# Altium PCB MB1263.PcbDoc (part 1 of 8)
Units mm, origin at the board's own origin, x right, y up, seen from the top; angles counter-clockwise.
Board outline 86 x 120 mm, 6 copper layers (Top Layer, Signal Layer 1, Signal Layer 2, Signal Layer 3, Signal Layer 4, Bottom Layer), stack 1.556 mm thick; 392 components, 421 nets, 1978 pads, 1444 vias.
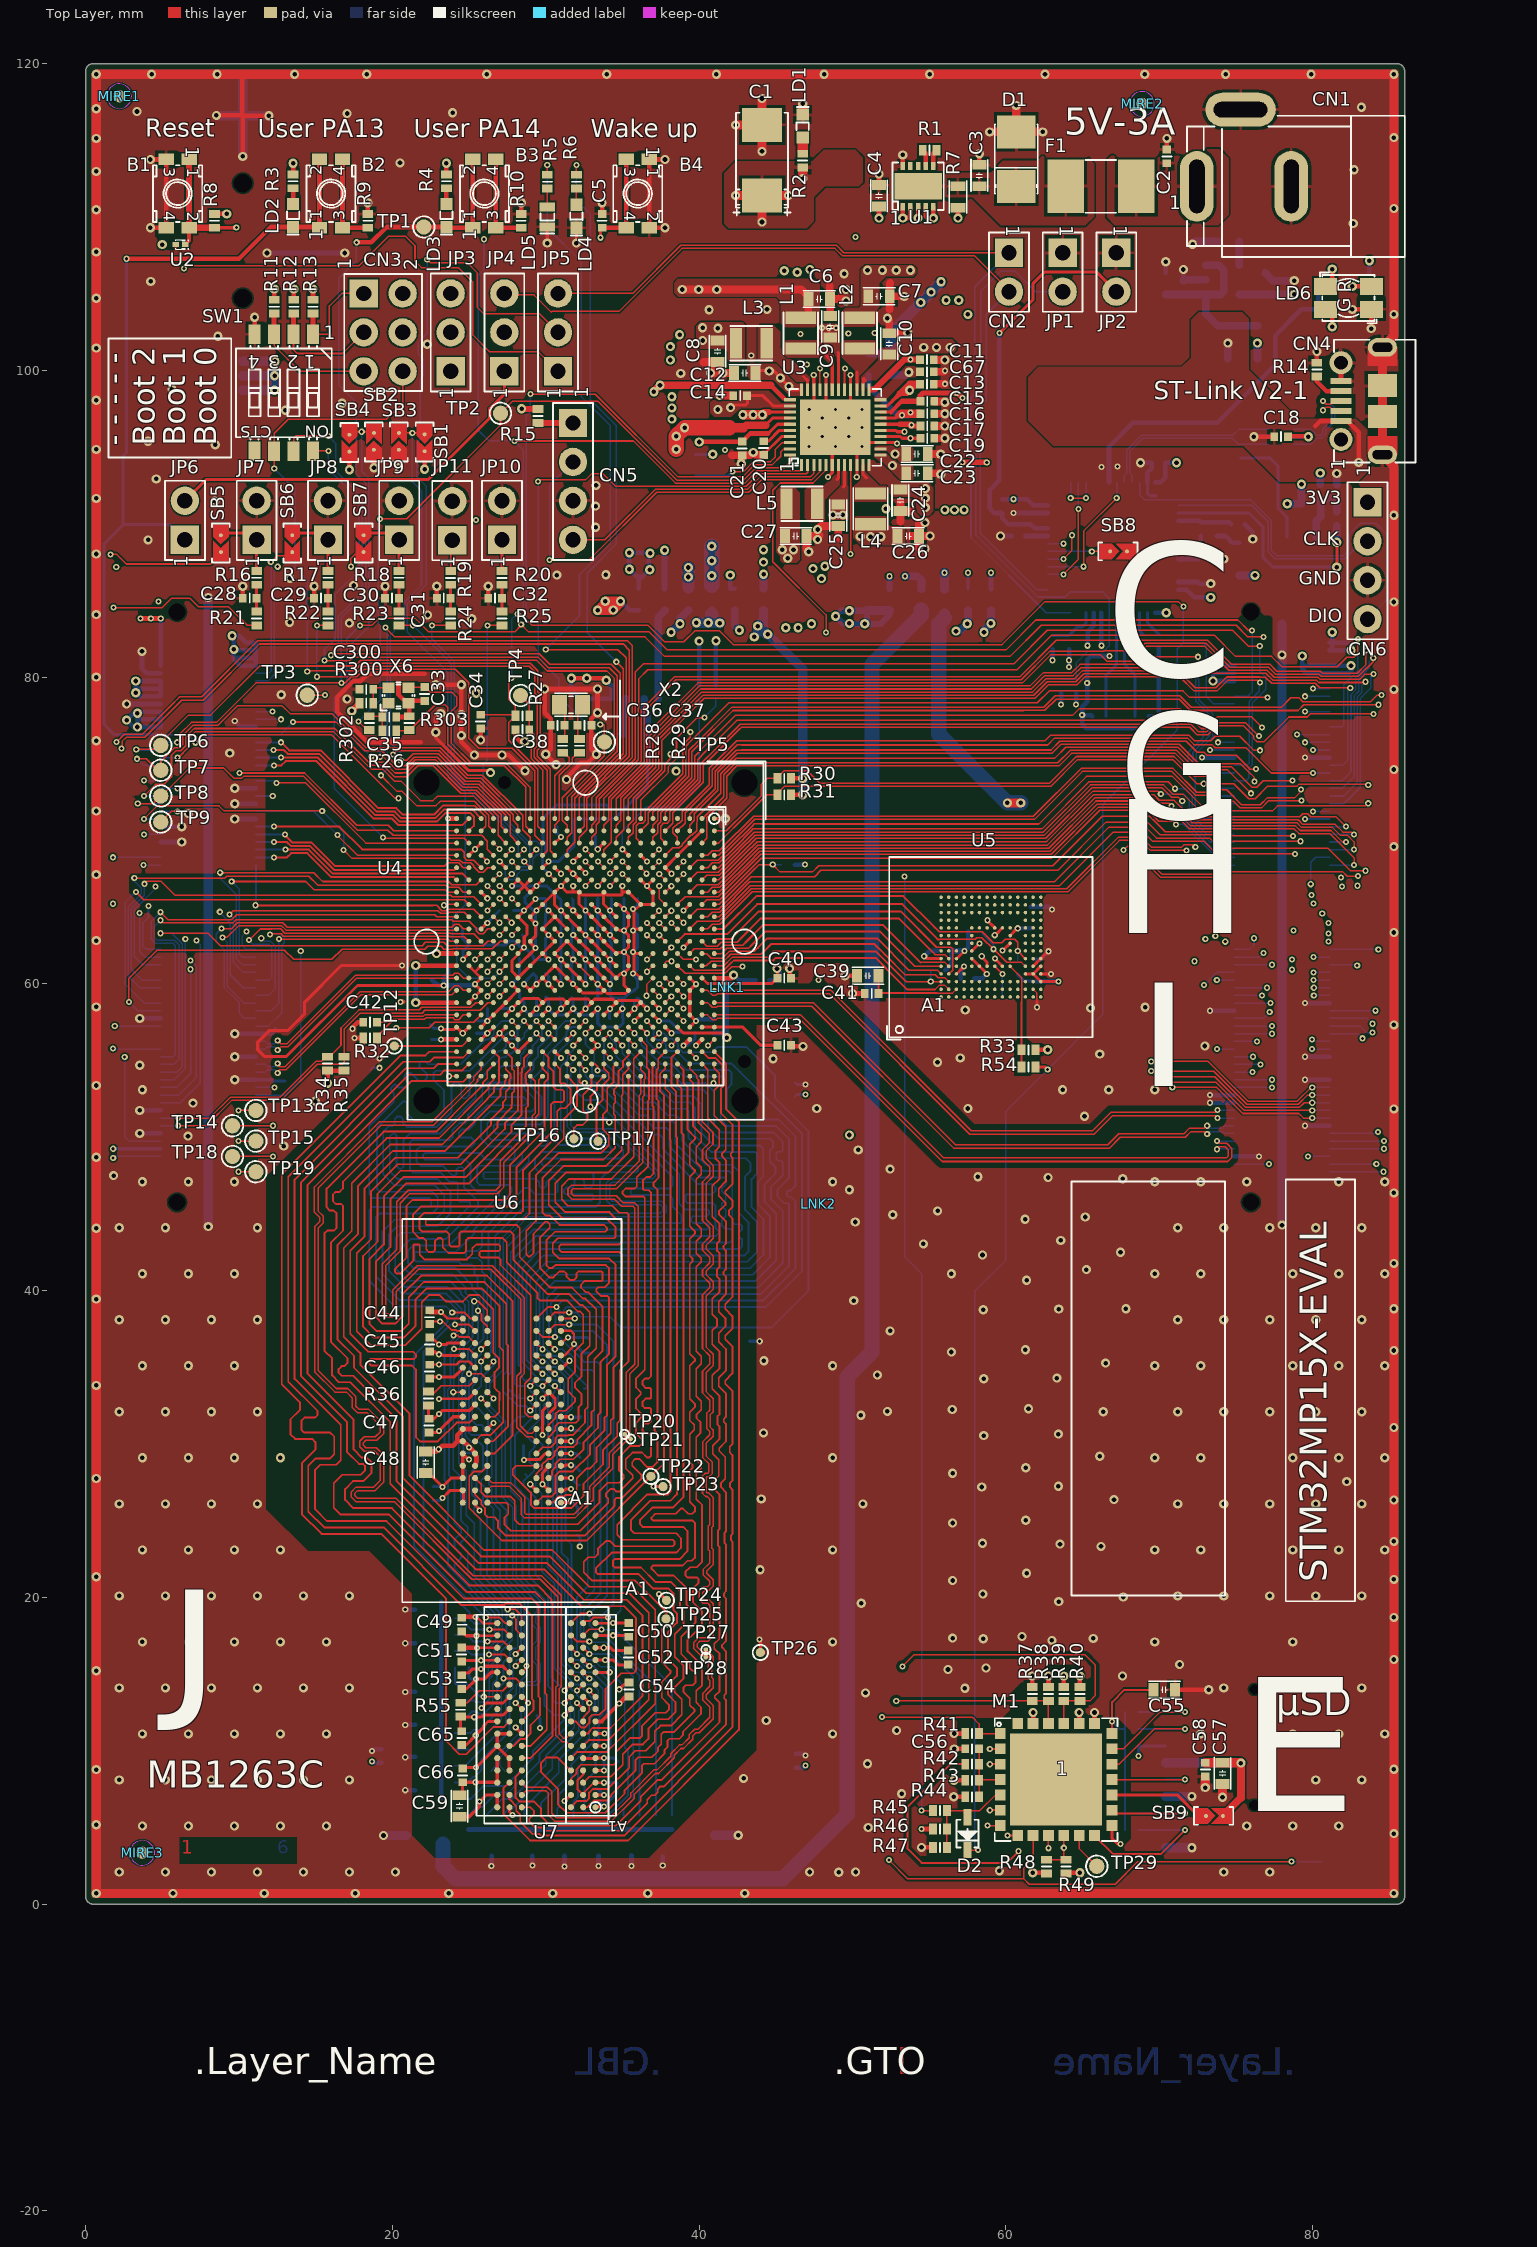
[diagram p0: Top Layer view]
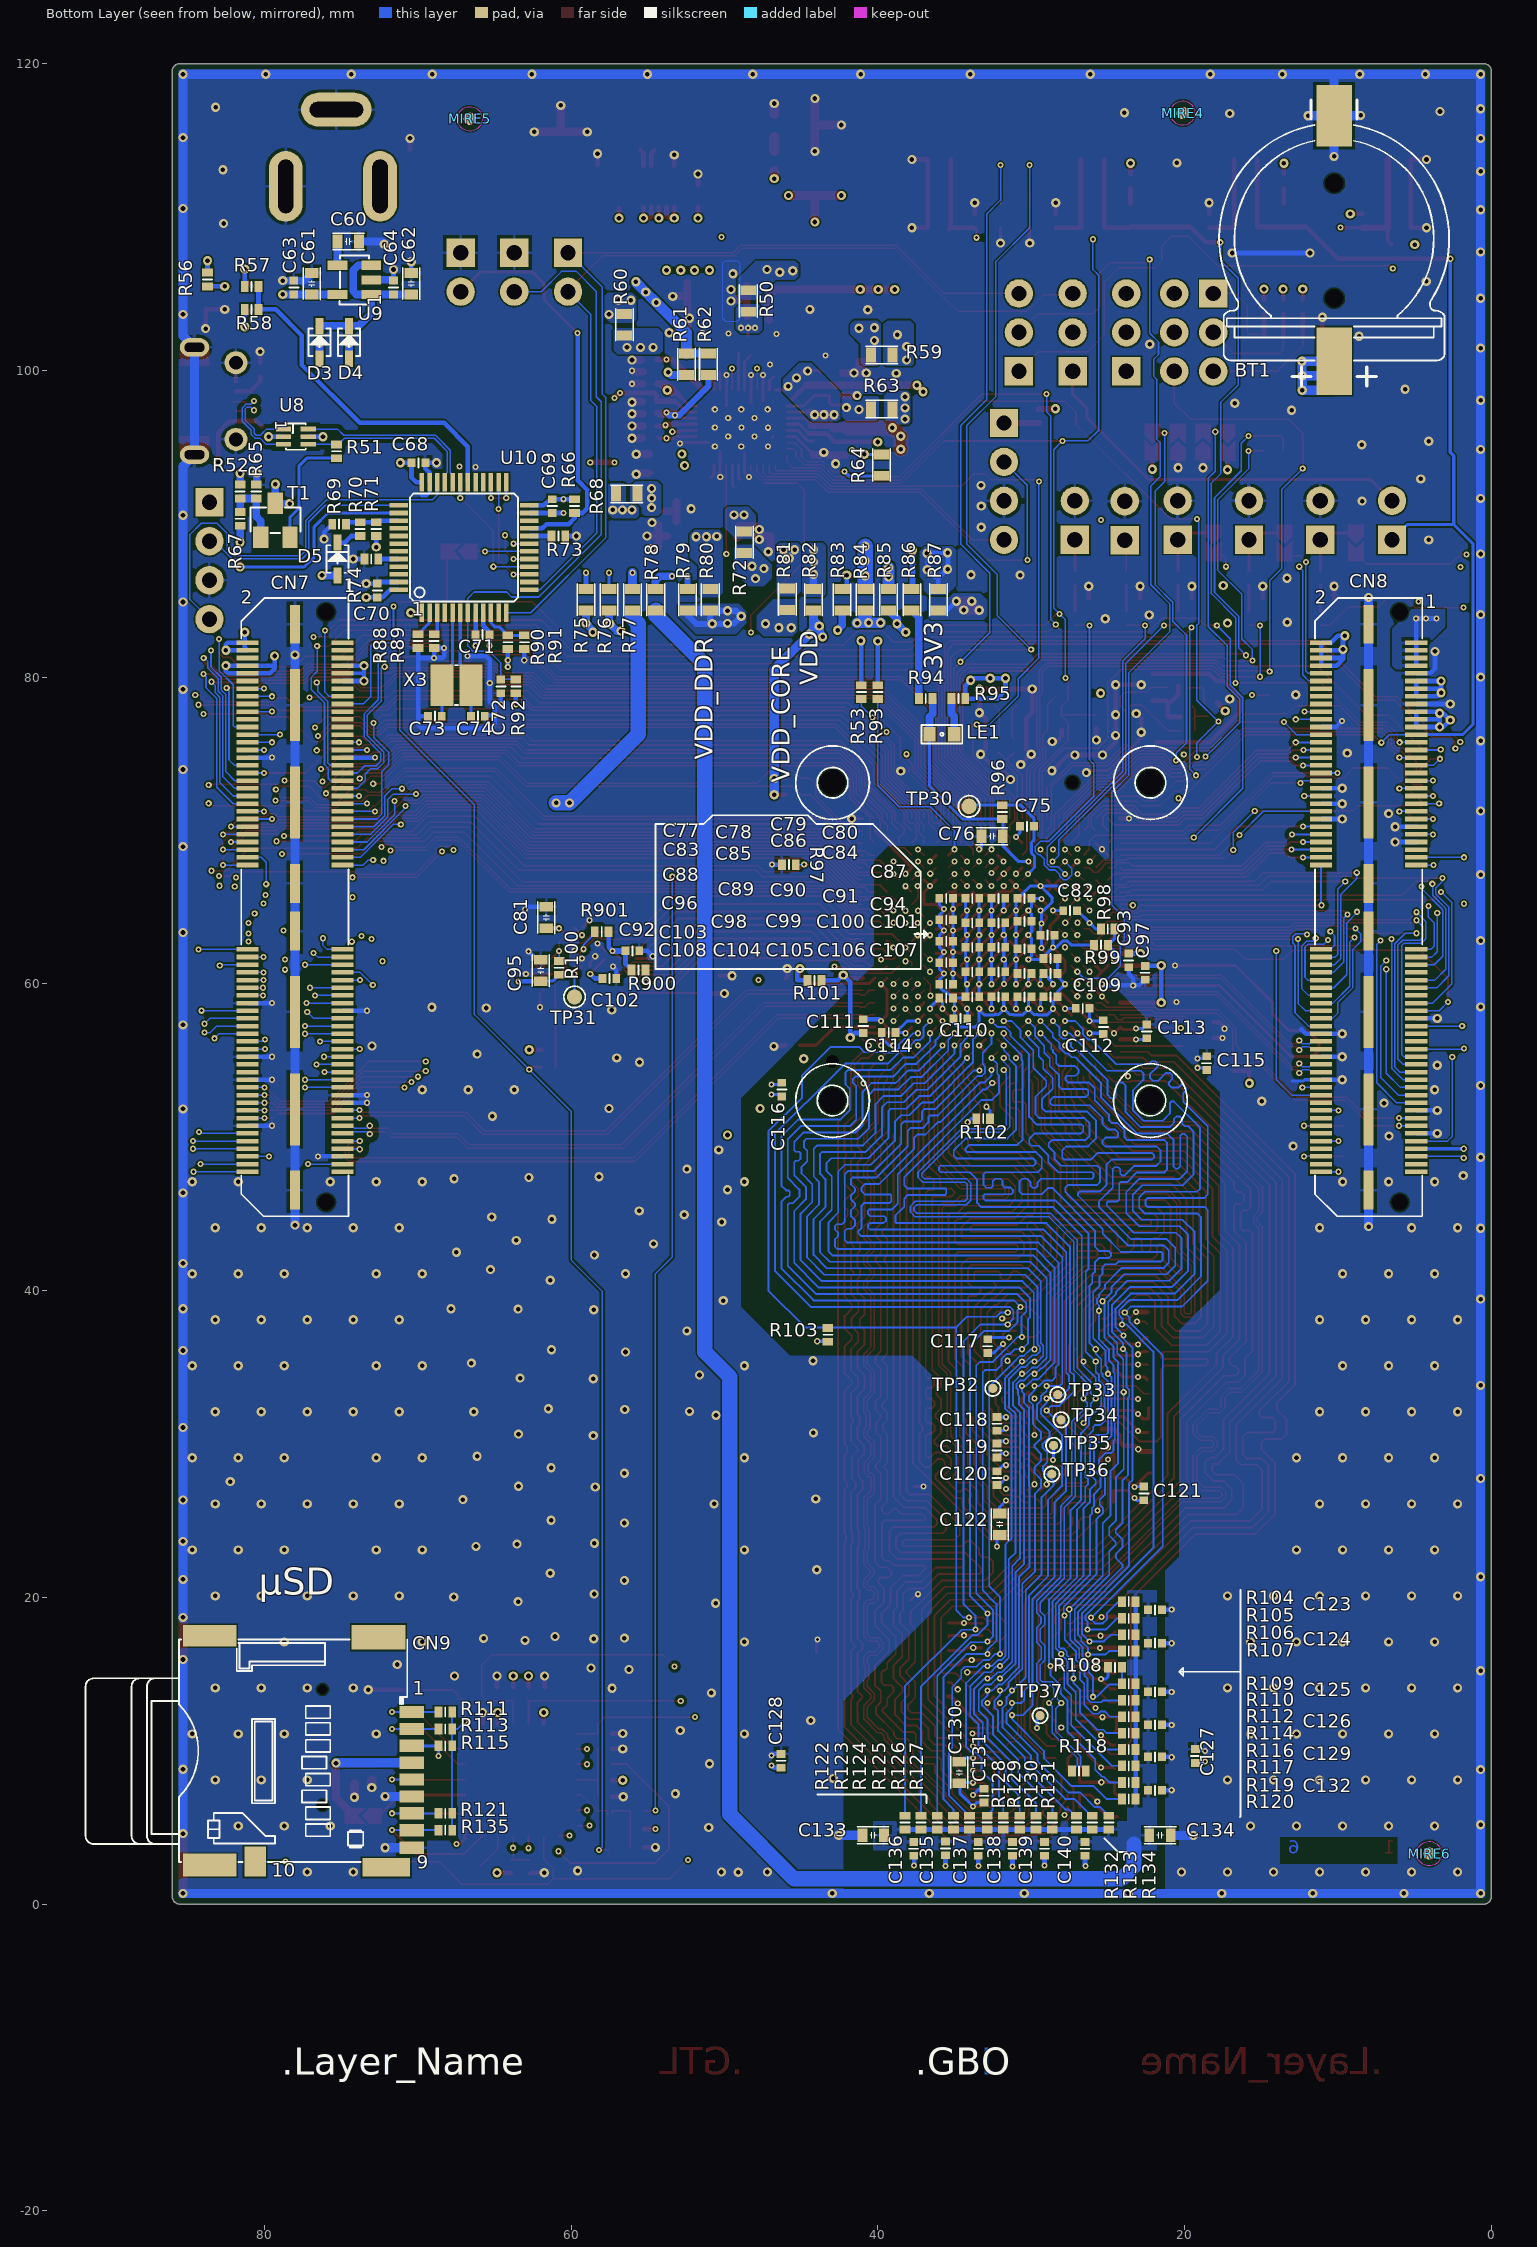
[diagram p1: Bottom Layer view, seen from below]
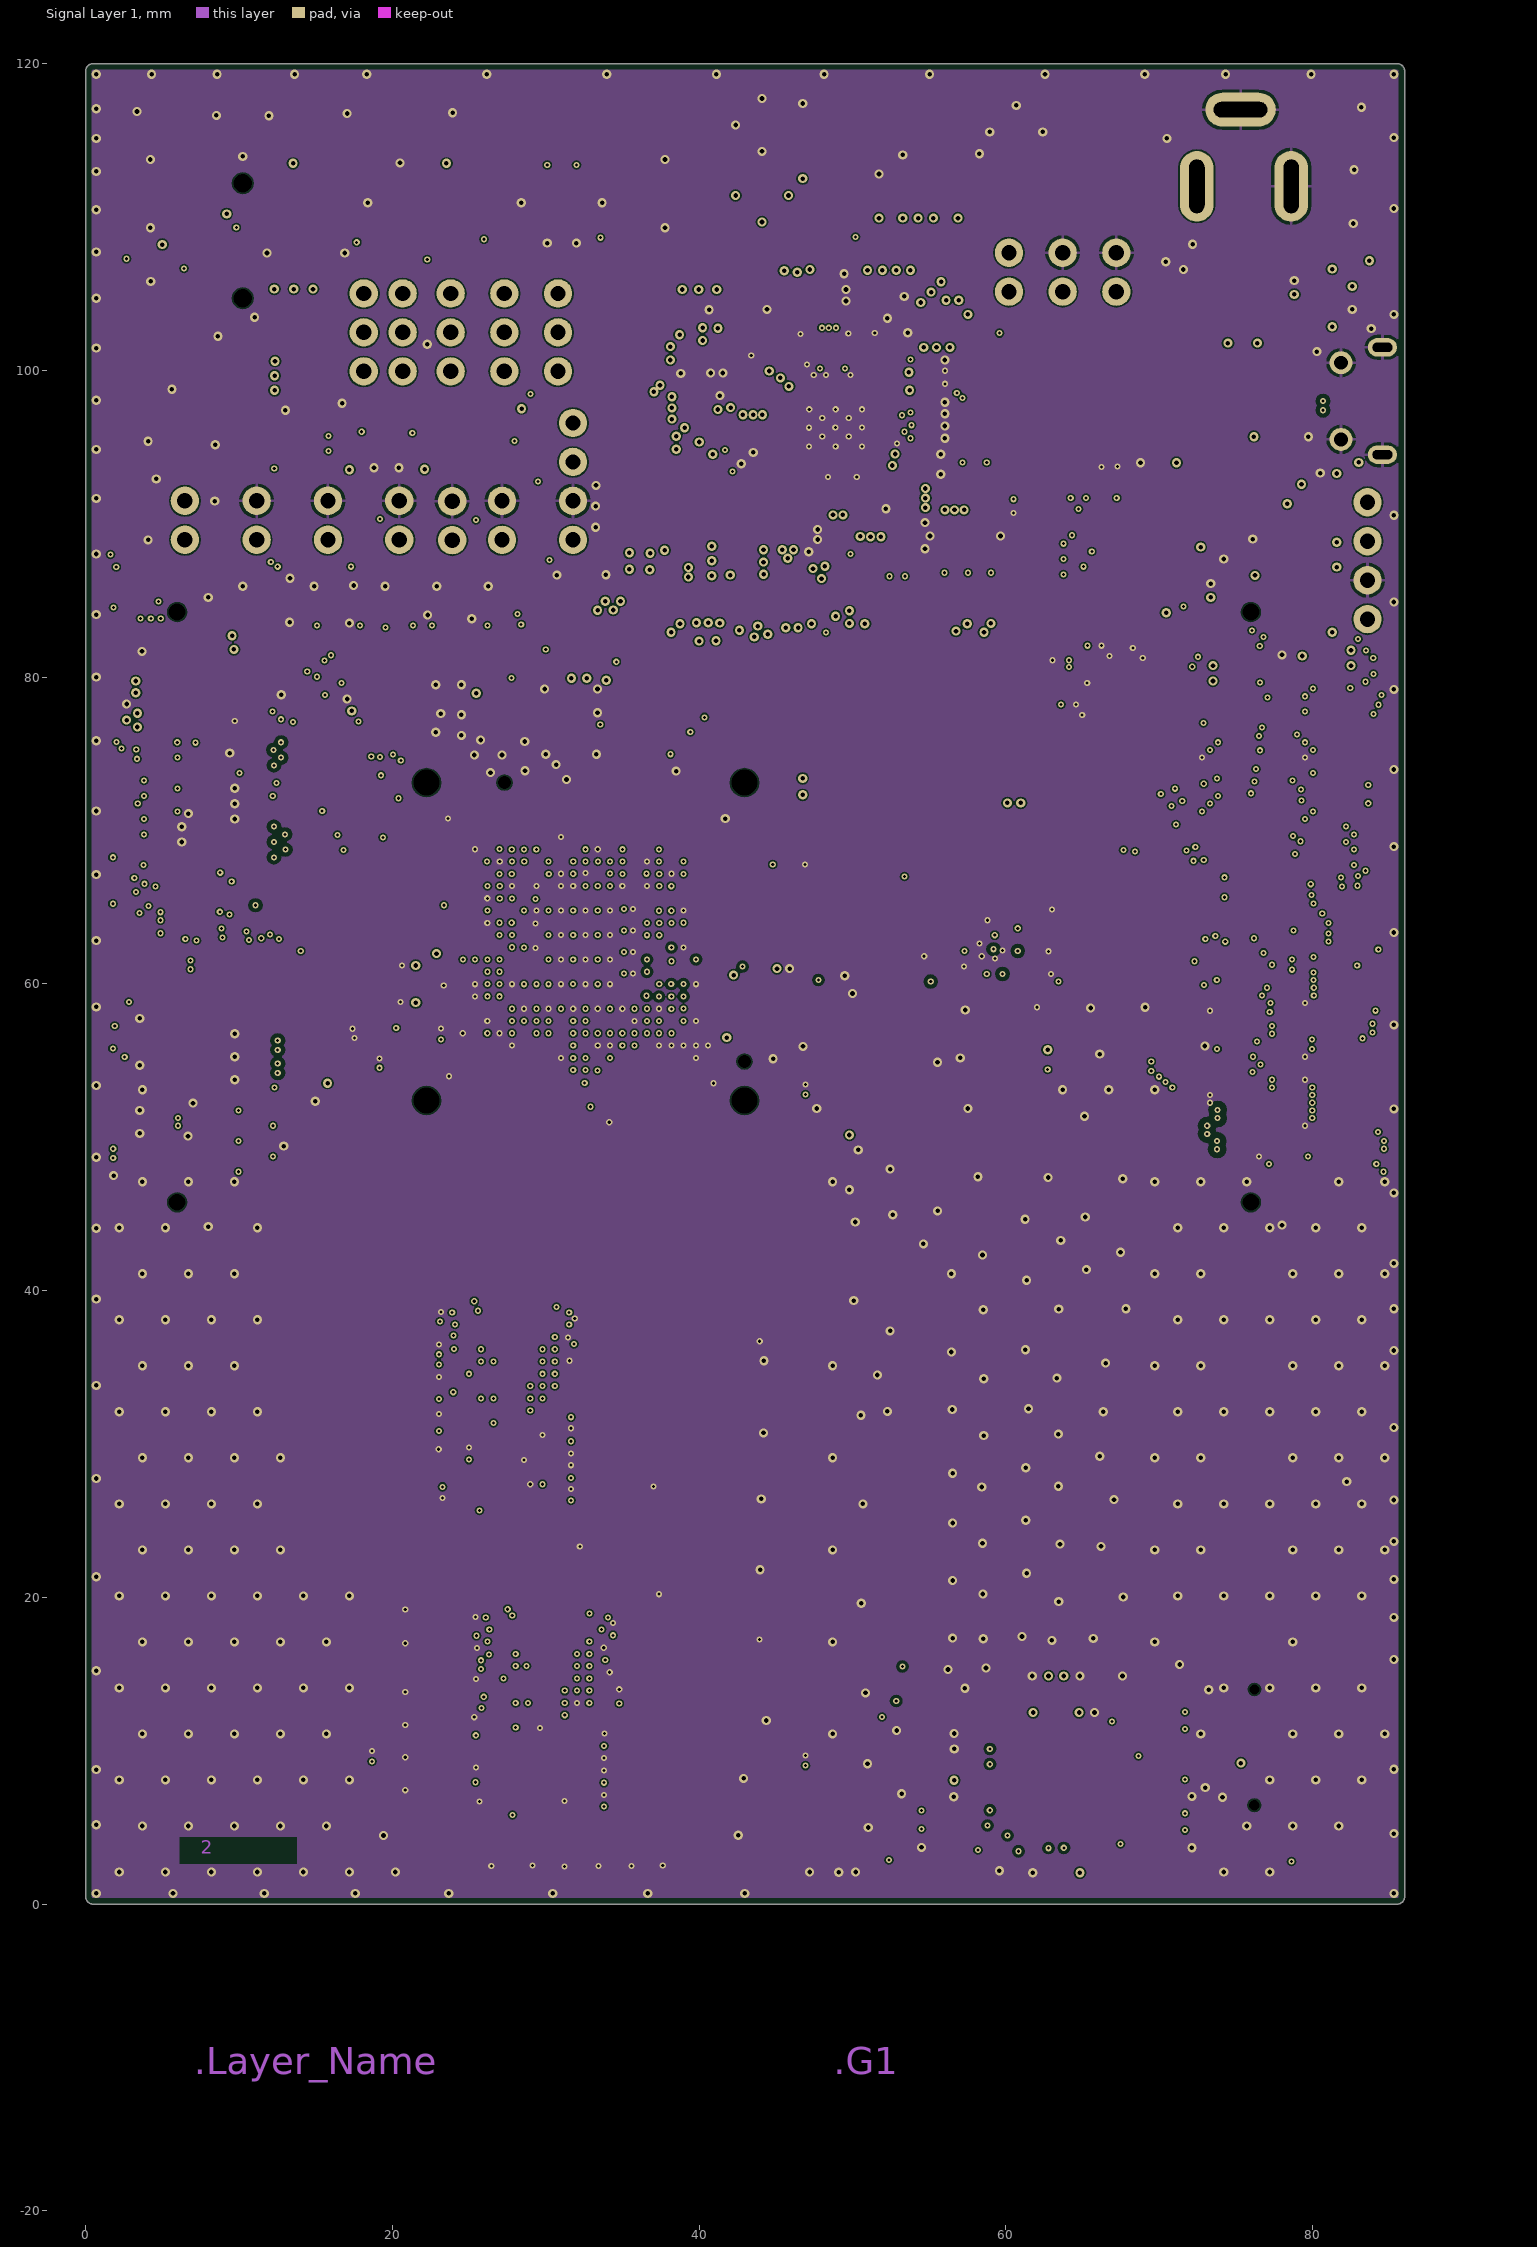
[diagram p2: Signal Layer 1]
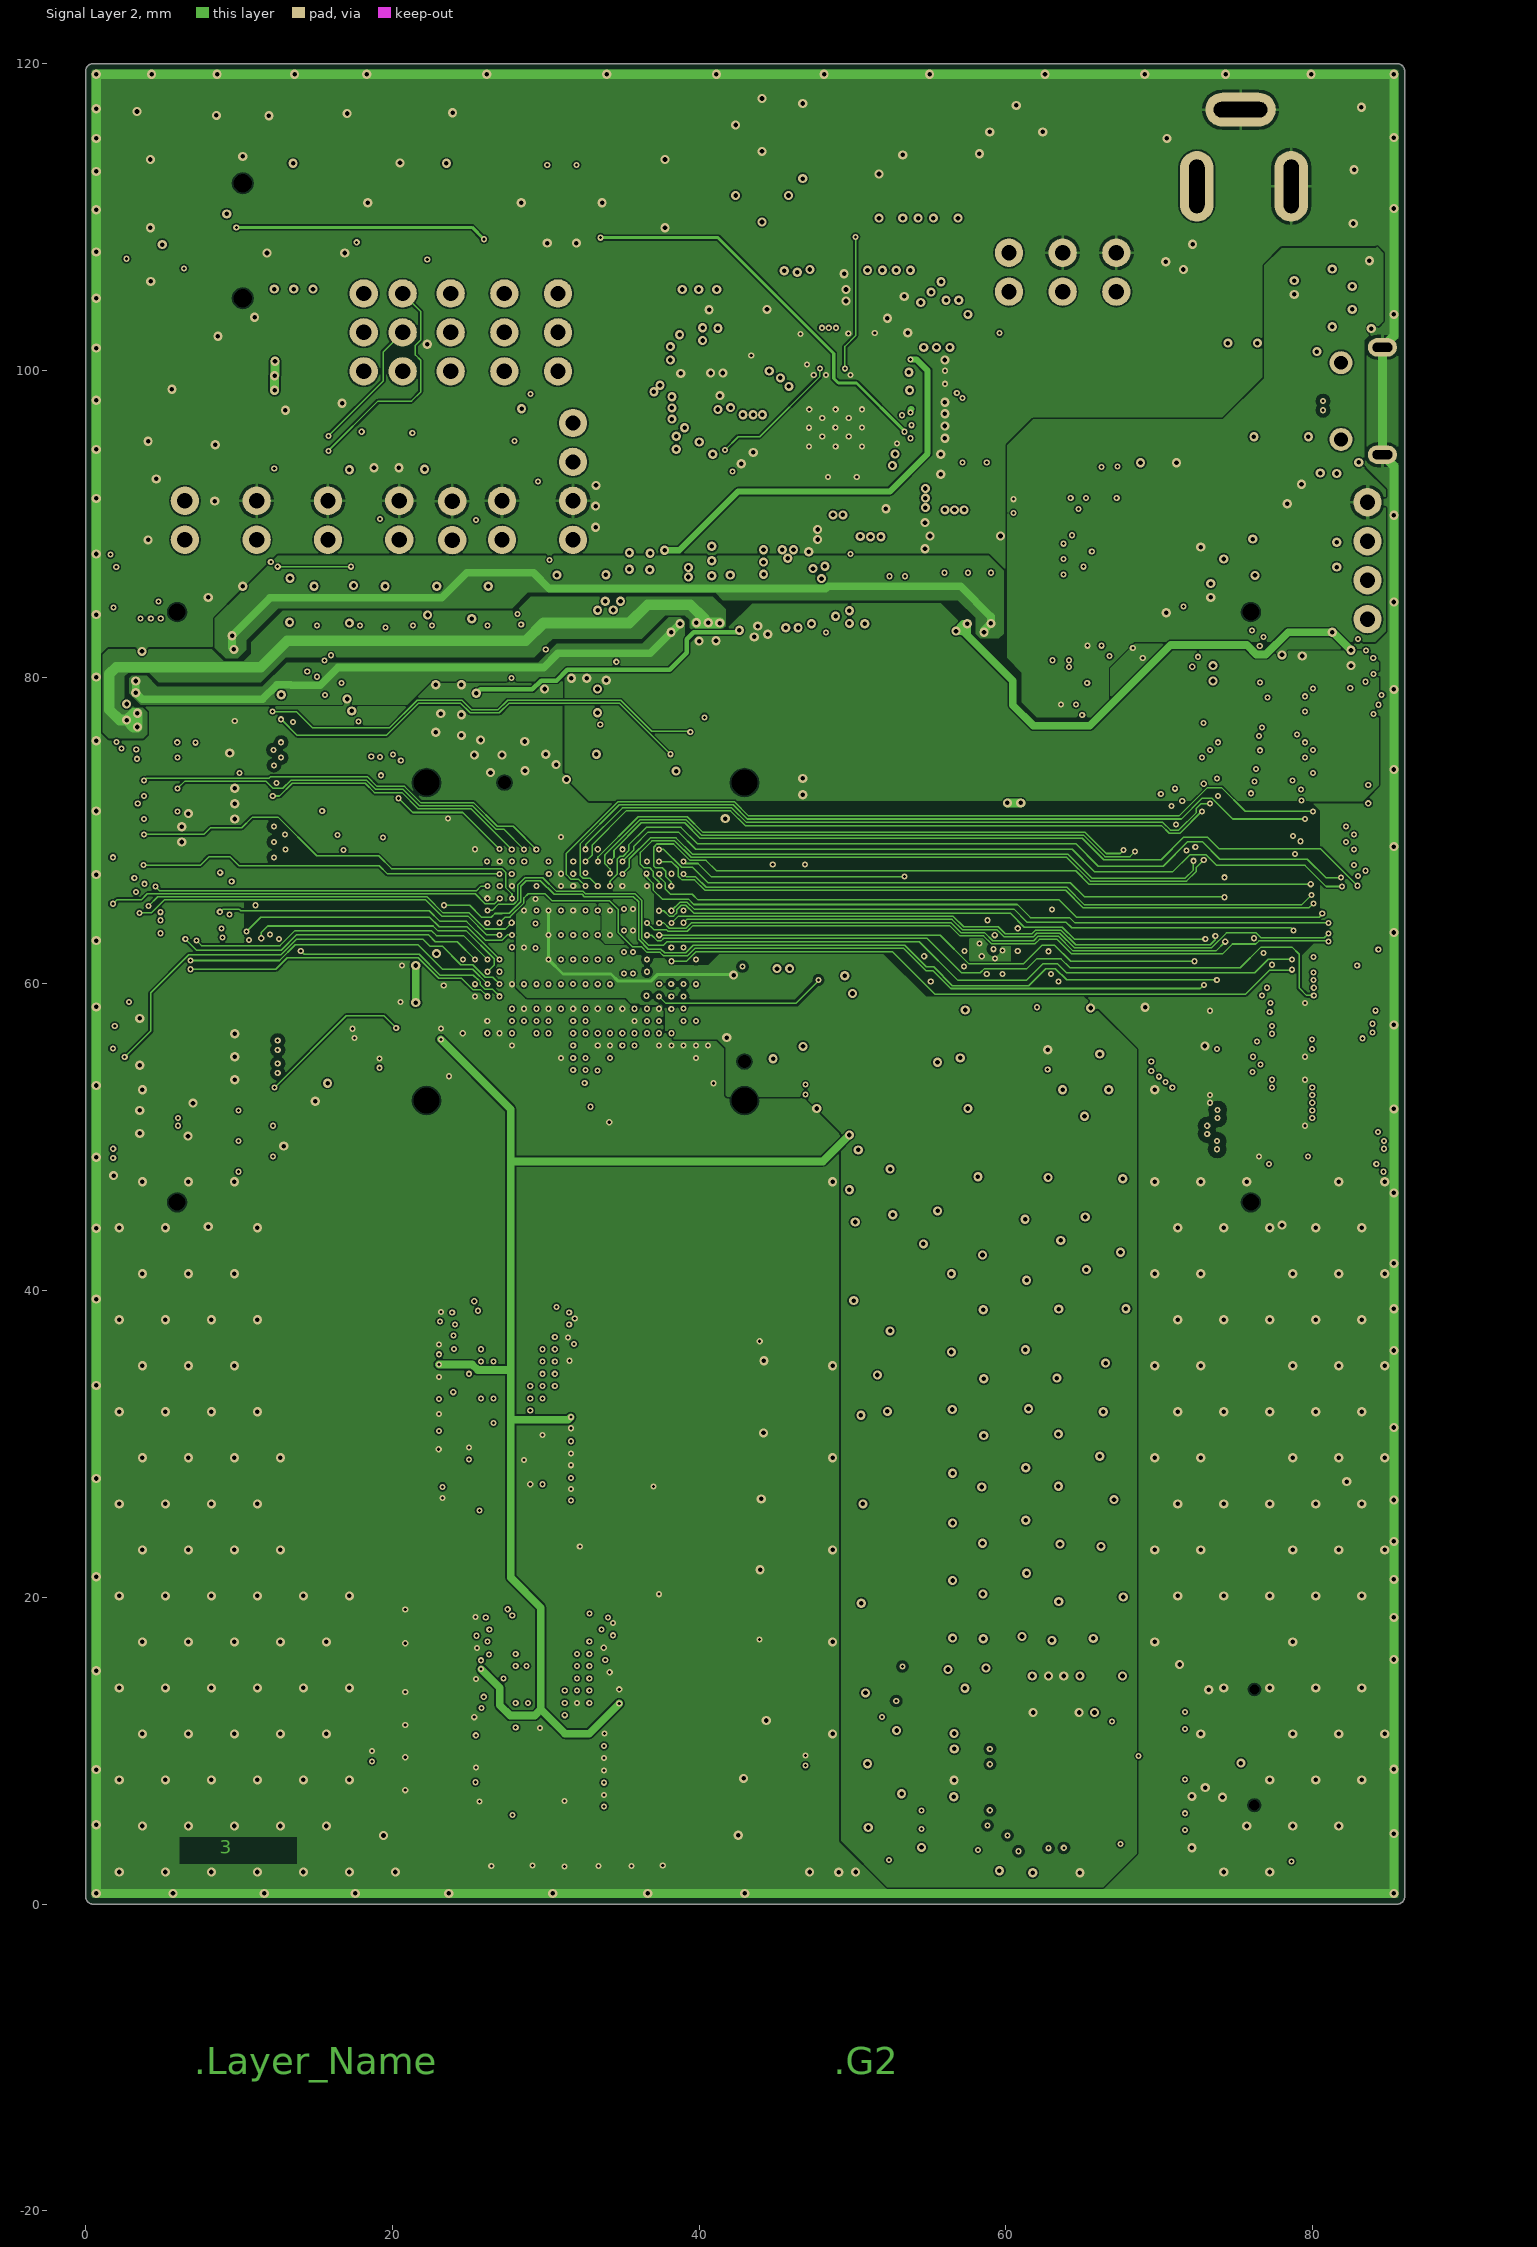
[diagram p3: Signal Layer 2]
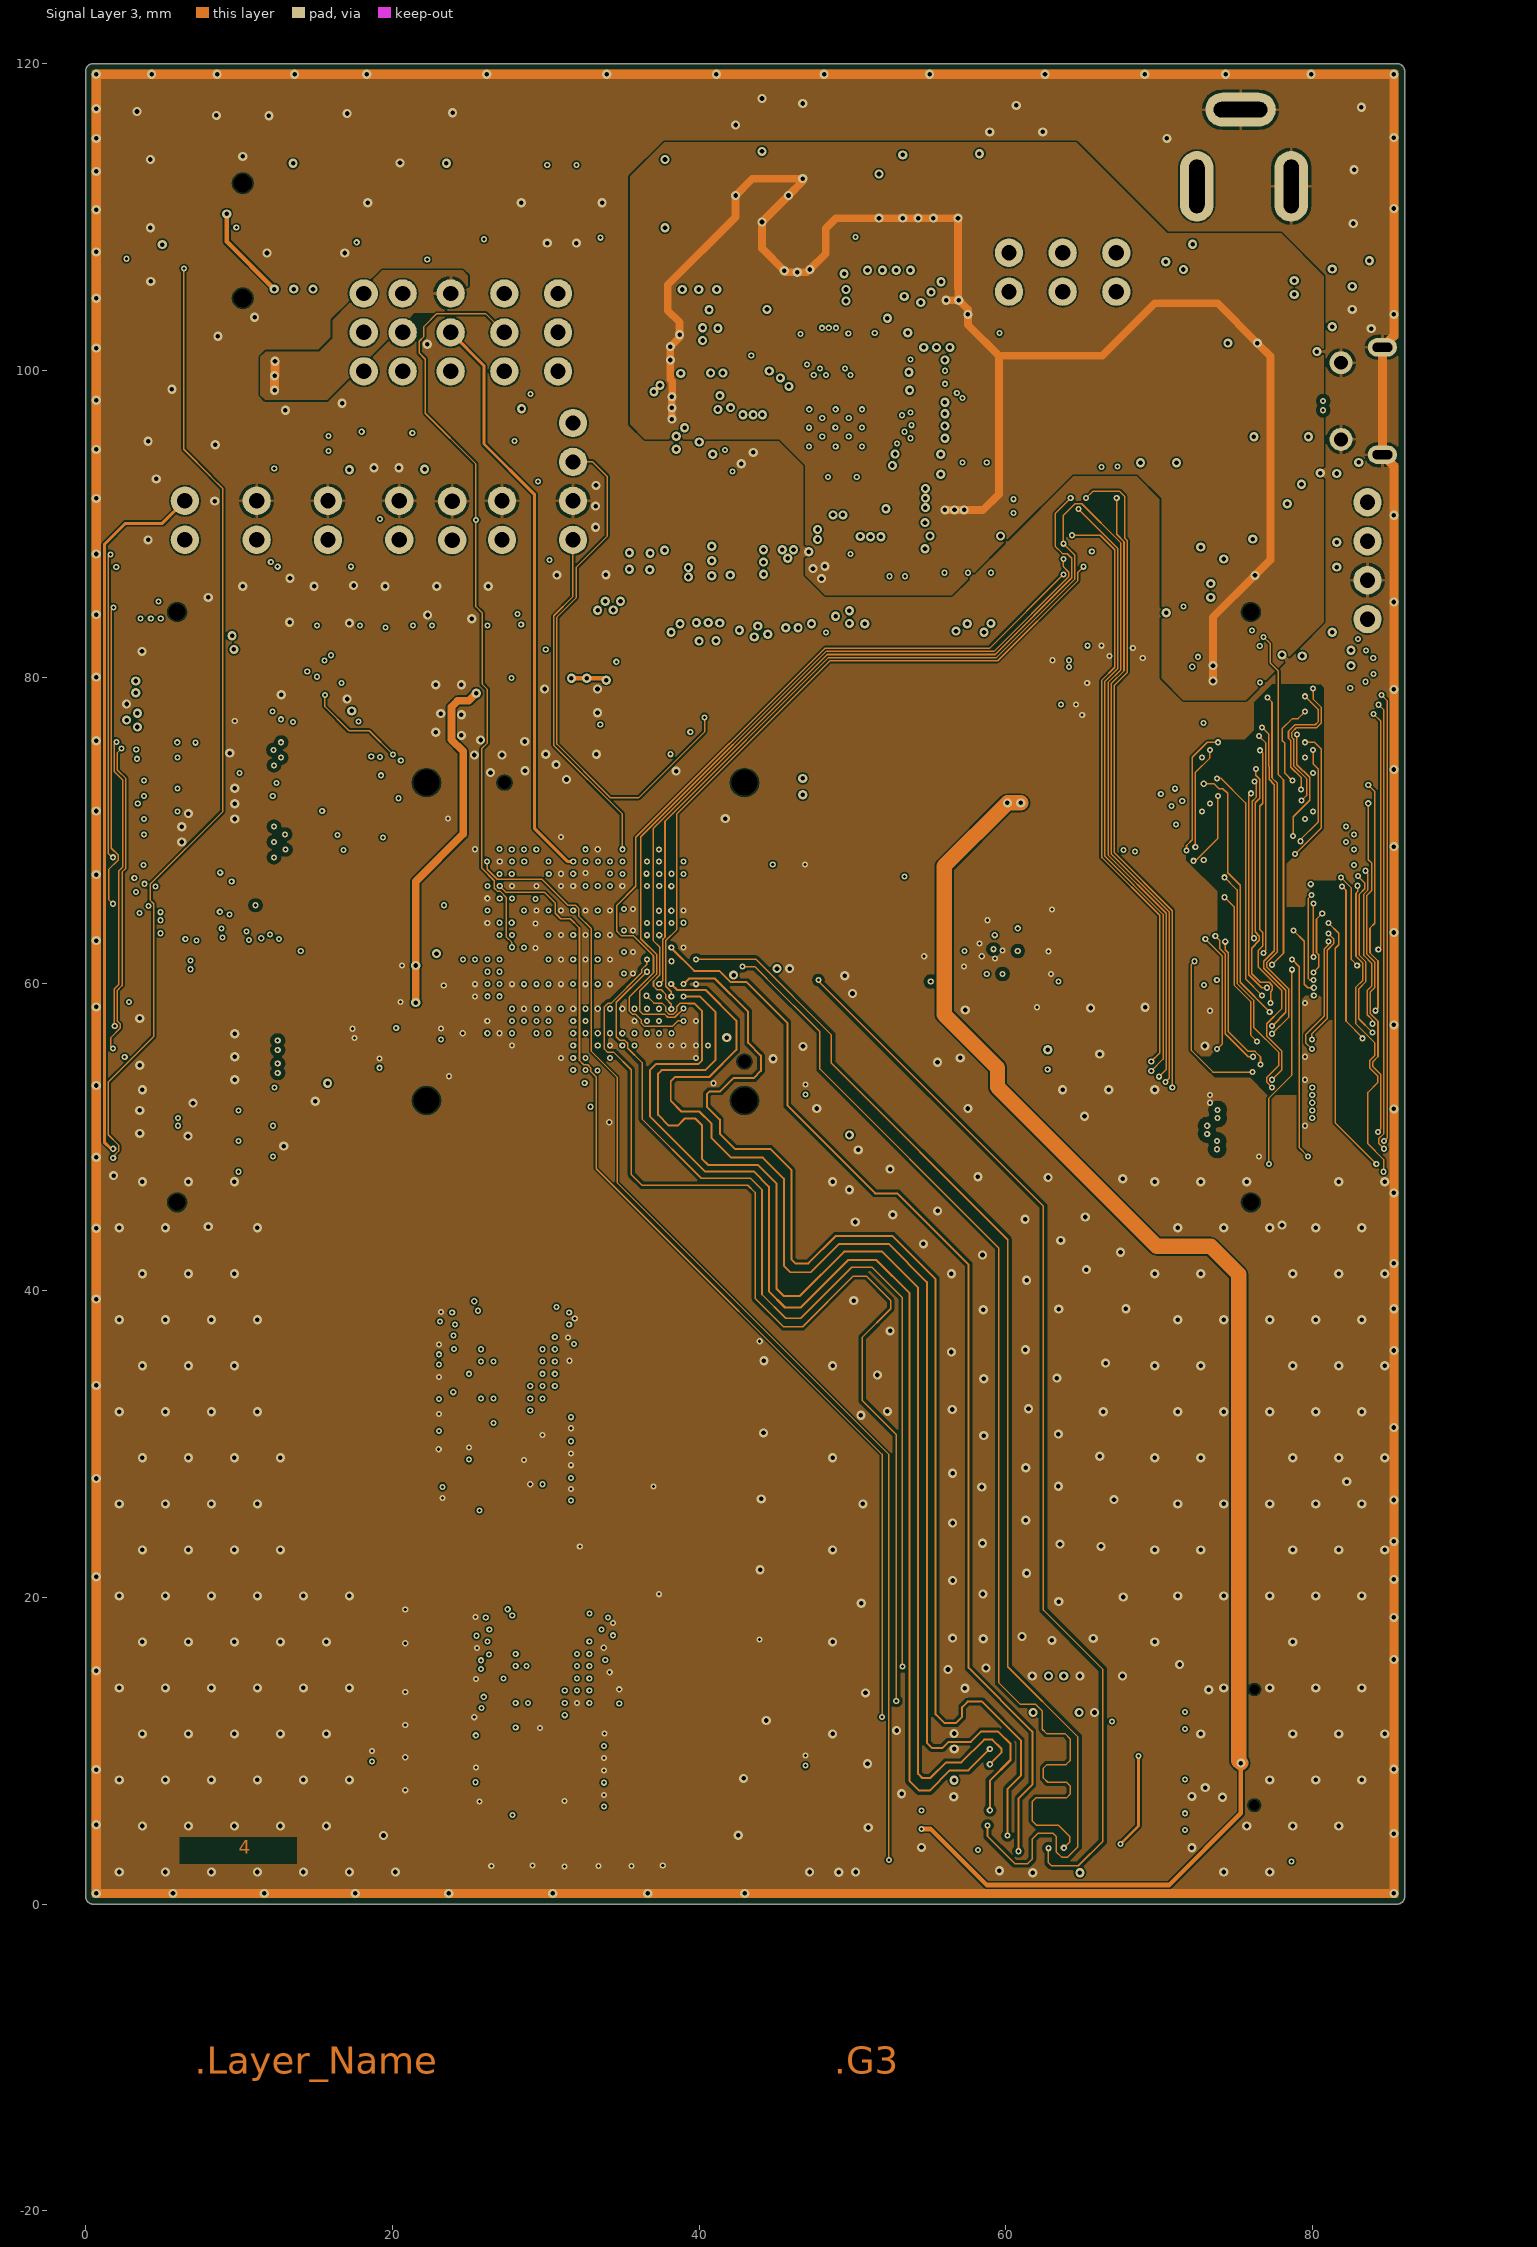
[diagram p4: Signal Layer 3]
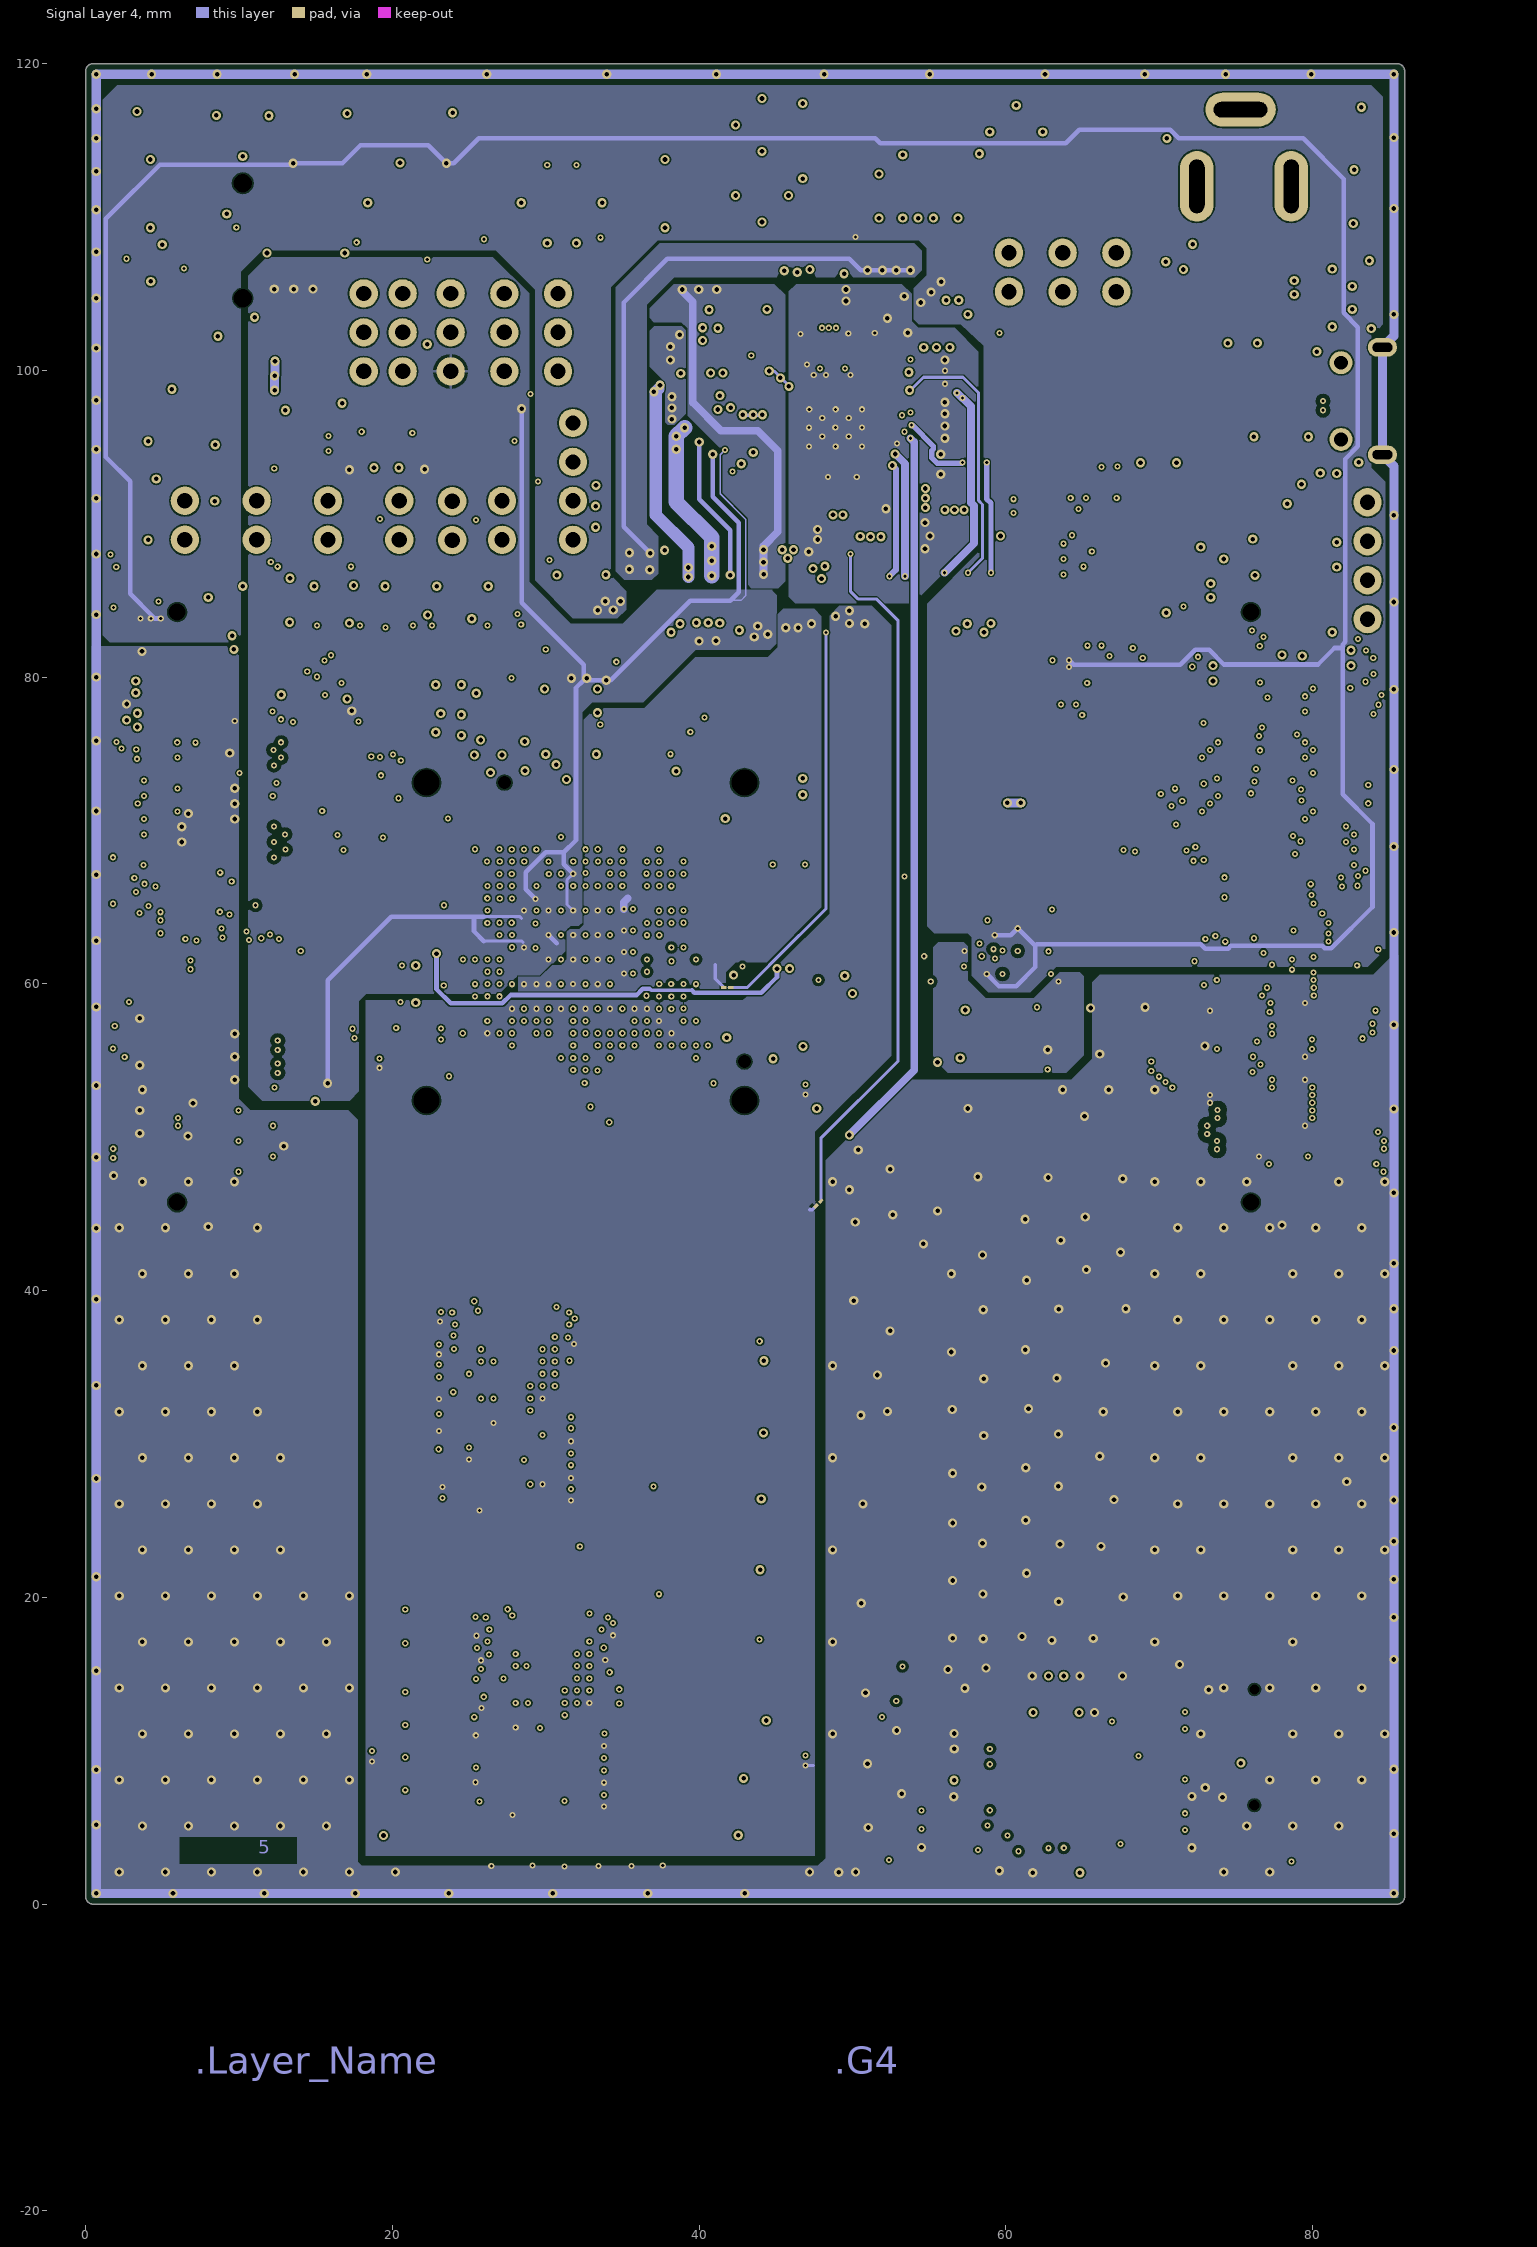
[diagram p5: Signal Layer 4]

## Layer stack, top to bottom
Top Solder: solder mask 0.0203, Solder Resist, Dk 3.5
Top Layer: signal copper 0.037
Dielectric 1: core 0.0986, FR-4, Dk 4.1
Signal Layer 1: signal copper 0.035
Dielectric 2: prepreg 0.13, Dk 4.25
Signal Layer 2: signal copper 0.035
Dielectric 3: core 0.885, Dk 4.25
Signal Layer 3: signal copper 0.035
Dielectric 4: prepreg 0.13, Dk 4.25
Signal Layer 4: signal copper 0.035
Dielectric 5: core 0.0986, Dk 4.1
Bottom Layer: signal copper 0.037
Bottom Solder: solder mask 0.0203, Solder Resist, Dk 3.5

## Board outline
0,0.5 0,119.5 cw(c0.5,119.5) 0.5,120 85.5,120 cw(c85.5,119.5) 86,119.5 86,0.5 cw(c85.5,0.5) 85.5,0 0.5,0 cw(c0.5,0.5)

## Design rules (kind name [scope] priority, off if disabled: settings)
BoardOutlineClearance [All] p1: gap=0.4 ignorepadtopadclearanceinfootprint=FALSE
Clearance Clearance_EMMC [InNetClass('NETC_EMMC')] p1: gap=0.1 ignorepadtopadclearanceinfootprint=FALSE except(0: Arc-Hole Track-Hole SMDPad-Hole THPad-Hole Via-Hole Fill-Hole Poly-Hole Region-Hole Text-Hole; 0.09: Track-SMDPad; 0.15: Arc-Fill Track-Fill SMDPad-Fill THPad-Fill Via-Fill Fill-Fill; 0.2: Arc-THPad Track-THPad SMDPad-SMDPad SMDPad-THPad THPad-THPad; 0.26: Arc-Poly Track-Poly SMDPad-Poly THPad-Poly Via-Poly Fill-Poly Poly-Poly)
Clearance Clearance_RGMII_TXD [InNetClass('NETC_RGMII_TXD')] p2: gap=0.1 ignorepadtopadclearanceinfootprint=FALSE except(0: Arc-Hole Track-Hole SMDPad-Hole THPad-Hole Via-Hole Fill-Hole Poly-Hole Region-Hole Text-Hole; 0.15: Arc-Fill Arc-Region Track-Fill Track-Region SMDPad-Fill SMDPad-Region THPad-Fill THPad-Region Via-Fill Via-Region Fill-Fill Fill-Region Poly-Region Region-Region; 0.2: Arc-THPad Track-THPad SMDPad-SMDPad SMDPad-THPad THPad-THPad; 0.26: Arc-Poly Track-Poly SMDPad-Poly THPad-Poly Via-Poly Fill-Poly Poly-Poly)
Clearance Clearance_RGMII_RXD [InNetClass('NETC_RGMII_RXD')] p3: gap=0.1 ignorepadtopadclearanceinfootprint=FALSE except(0: Arc-Hole Track-Hole SMDPad-Hole THPad-Hole Via-Hole Fill-Hole Poly-Hole Region-Hole Text-Hole; 0.15: Arc-Fill Arc-Region Track-Fill Track-Region SMDPad-Fill SMDPad-Region THPad-Fill THPad-Region Via-Fill Via-Region Fill-Fill Fill-Region Poly-Region Region-Region; 0.2: Arc-THPad Track-THPad SMDPad-SMDPad SMDPad-THPad THPad-THPad; 0.26: Arc-Poly Track-Poly SMDPad-Poly THPad-Poly Via-Poly Fill-Poly Poly-Poly)
Clearance Clearance_USB [InNetClass('NETC_USB')] p4: gap=0.1 ignorepadtopadclearanceinfootprint=FALSE except(0: Arc-Hole Track-Hole SMDPad-Hole THPad-Hole Via-Hole Fill-Hole Poly-Hole Region-Hole Text-Hole; 0.09: Track-Track; 0.15: Arc-Fill Arc-Region Track-Fill Track-Region SMDPad-Fill SMDPad-Region THPad-Fill THPad-Region Via-Fill Via-Region Fill-Fill Fill-Region Poly-Region Region-Region; 0.2: Arc-THPad Track-THPad SMDPad-SMDPad SMDPad-THPad THPad-THPad; 0.27: Arc-Poly Track-Poly SMDPad-Poly THPad-Poly Via-Poly Fill-Poly Poly-Poly)
Clearance Clearance_DSI [InNetClass('NETC_DSI')] p5: gap=0.1 ignorepadtopadclearanceinfootprint=FALSE except(0: Arc-Hole Track-Hole SMDPad-Hole THPad-Hole Via-Hole Fill-Hole Poly-Hole Region-Hole Text-Hole; 0.15: Arc-Fill Arc-Region Track-Fill Track-Region SMDPad-Fill SMDPad-Region THPad-Fill THPad-Region Via-Fill Via-Region Fill-Fill Fill-Region Poly-Region Region-Region; 0.2: Arc-THPad Track-THPad SMDPad-SMDPad SMDPad-THPad THPad-THPad; 0.39: Arc-Poly Track-Poly SMDPad-Poly THPad-Poly Via-Poly Fill-Poly Poly-Poly)
Clearance Clearance_SDMMC1 [InNetClass('NETC_SDMMC1')] p6: gap=0.1 ignorepadtopadclearanceinfootprint=FALSE except(0: Arc-Hole Track-Hole SMDPad-Hole THPad-Hole Via-Hole Fill-Hole Poly-Hole Region-Hole Text-Hole; 0.15: Arc-Fill Arc-Region Track-Fill Track-Region SMDPad-Fill SMDPad-Region THPad-Fill THPad-Region Via-Fill Via-Region Fill-Fill Fill-Region Poly-Region Region-Region; 0.2: Arc-THPad Arc-Poly Track-THPad Track-Poly SMDPad-SMDPad SMDPad-THPad SMDPad-Poly THPad-THPad THPad-Poly Via-Poly Fill-Poly Poly-Poly)
Clearance Clearance_SDMMC1_CLK [InNetClass('NETC_CLK')] p7: gap=0.2 ignorepadtopadclearanceinfootprint=FALSE except(0: Arc-Hole Track-Hole SMDPad-Hole THPad-Hole Via-Hole Fill-Hole Poly-Hole Region-Hole Text-Hole; 0.1: Arc-Arc Arc-Track Arc-SMDPad Arc-Via Arc-Text Track-Track Track-SMDPad Track-Via Track-Text SMDPad-Via SMDPad-Text THPad-Via THPad-Text Via-Via Via-Text Fill-Text Poly-Text Region-Text Text-Text)
Clearance Clearance_EMMC_GND [InNet('GND')] p8: gap=0.1 ignorepadtopadclearanceinfootprint=FALSE except(0: Arc-Hole Track-Hole SMDPad-Hole THPad-Hole Via-Hole Fill-Hole Poly-Hole Region-Hole Text-Hole; 0.09: Track-SMDPad; 0.15: Arc-Fill Track-Fill SMDPad-Fill THPad-Fill Via-Fill Fill-Fill; 0.2: Arc-THPad Track-THPad SMDPad-SMDPad SMDPad-THPad THPad-THPad)
Clearance [All] p9: gap=0.1 ignorepadtopadclearanceinfootprint=FALSE except(0: Arc-Hole Track-Hole SMDPad-Hole THPad-Hole Via-Hole Fill-Hole Poly-Hole Region-Hole Text-Hole; 0.15: Arc-Fill Track-Fill SMDPad-Fill THPad-Fill Via-Fill Fill-Fill; 0.2: Arc-THPad Track-THPad SMDPad-SMDPad SMDPad-THPad THPad-THPad)
ComponentClearance [All] p1 off: gap=0.025 collisioncheckmode=3 verticalgap=2540 showdistances=TRUE
DiffPairsRouting DiffPairsRouting_DDR [InDifferentialPairClass('DIFF_DDR')] p1: maxlimit=0.13 minlimit=0.13 mostfreqgap=0.13 toplayer_minwidth=0.1 toplayer_maxwidth=0.1 toplayer_prefwidth=0.1 midlayer1_minwidth=0.1 midlayer1_maxwidth=0.1 midlayer1_prefwidth=0.1 midlayer2_minwidth=0.1 midlayer2_maxwidth=0.1 midlayer2_prefwidth=0.1 midlayer3_minwidth=0.1 midlayer3_maxwidth=0.1 midlayer3_prefwidth=0.1 midlayer4_minwidth=0.1 midlayer4_maxwidth=0.1 midlayer4_prefwidth=0.1 bottomlayer_minwidth=0.1 bottomlayer_maxwidth=0.1 bottomlayer_prefwidth=0.1 maxuncoupledlength=12.7
DiffPairsRouting DiffPairsRouting_DSI [InDifferentialPairClass('DIFF_DSI')] p2: maxlimit=0.13 minlimit=0.13 mostfreqgap=0.13 toplayer_minwidth=0.1 toplayer_maxwidth=0.1 toplayer_prefwidth=0.1 midlayer1_minwidth=0.1 midlayer1_maxwidth=0.1 midlayer1_prefwidth=0.1 midlayer2_minwidth=0.1 midlayer2_maxwidth=0.1 midlayer2_prefwidth=0.1 midlayer3_minwidth=0.1 midlayer3_maxwidth=0.1 midlayer3_prefwidth=0.1 midlayer4_minwidth=0.1 midlayer4_maxwidth=0.1 midlayer4_prefwidth=0.1 bottomlayer_minwidth=0.1 bottomlayer_maxwidth=0.1 bottomlayer_prefwidth=0.1 maxuncoupledlength=12.7
DiffPairsRouting DiffPairsRouting_USB [InDifferentialPairClass('DIFF_USB')] p3: maxlimit=0.09 minlimit=0.09 mostfreqgap=0.09 toplayer_minwidth=0.1 toplayer_maxwidth=0.1 toplayer_prefwidth=0.1 midlayer1_minwidth=0.1 midlayer1_maxwidth=0.1 midlayer1_prefwidth=0.1 midlayer2_minwidth=0.1 midlayer2_maxwidth=0.1 midlayer2_prefwidth=0.1 midlayer3_minwidth=0.1 midlayer3_maxwidth=0.1 midlayer3_prefwidth=0.1 midlayer4_minwidth=0.1 midlayer4_maxwidth=0.1 midlayer4_prefwidth=0.1 bottomlayer_minwidth=0.1 bottomlayer_maxwidth=0.1 bottomlayer_prefwidth=0.1 maxuncoupledlength=12.7
FanoutControl Fanout_BGA [IsBGA] p1: bgadir=Out bgaviamode=Closest fanoutstyle=Auto fanoutdirection=Alternating viagrid=0.025 // Fanout_BGA (Default Rule)
FanoutControl Fanout_LCC [IsLCC] p2: bgadir=Out bgaviamode=Closest fanoutstyle=Auto fanoutdirection=Alternating viagrid=0.025 // Fanout_LCC (Default Rule)
FanoutControl Fanout_SOIC [IsSOIC] p3: bgadir=Out bgaviamode=Closest fanoutstyle=Auto fanoutdirection=Alternating viagrid=0.025 // Fanout_SOIC (Default Rule)
FanoutControl Fanout_Small [(CompPinCount < 5)] p4: bgadir=Out bgaviamode=Closest fanoutstyle=Auto fanoutdirection=OutThenIn viagrid=0.025 // Fanout_Small (Default Rule)
FanoutControl Fanout_Default [All] p5: bgadir=Out bgaviamode=Closest fanoutstyle=Auto fanoutdirection=Alternating viagrid=0.025 // Fanout_Default (Default Rule)
Height [All] p1 off: minheight=0 maxheight=100 prefheight=0.5
HoleSize [All] p1: absolutevalues=TRUE maxlimit=10 minlimit=0.15 maxpercent=80.000 minpercent=20.000
HoleToHoleClearance [All] p1: gap=0.25 allowstackedmicrovias=TRUE
Length Length_SDMMC1 [InNetClass('NETC_SDMMC1')] p1: maxlimit=86 minlimit=81
MatchedLengths [All] p1: tolerance=25.4 checknetsindiffpair=FALSE checkdiffpairvsdiffpair=TRUE checkxsignals=TRUE checkothers=TRUE
MinimumSolderMaskSliver [All] p1: minsoldermaskwidth=0
PlaneClearance [All] p1: clearance=0.6
PolygonConnect PolygonConnect_1 [All vs IsNamedPolygon('NO FT')] p1: thpad.connectstyle=Relief thpad.reliefconductorwidth=0.254 thpad.reliefentries=4 thpad.polygonreliefangle="90 Angle" thpad.airgapwidth=0.254 smdpad.connectstyle=Direct smdpad.reliefconductorwidth=0.254 smdpad.reliefentries=4 smdpad.polygonreliefangle="90 Angle" smdpad.airgapwidth=0.254 via.connectstyle=Direct via.reliefconductorwidth=0.254 via.reliefentries=4 via.polygonreliefangle="90 Angle" via.airgapwidth=0.254
PolygonConnect [All] p2: thpad.connectstyle=Relief thpad.reliefconductorwidth=0.2 thpad.reliefentries=4 thpad.polygonreliefangle="90 Angle" thpad.airgapwidth=0.2 smdpad.connectstyle=Relief smdpad.reliefconductorwidth=0.2 smdpad.reliefentries=4 smdpad.polygonreliefangle="90 Angle" smdpad.airgapwidth=0.2 via.connectstyle=Direct via.reliefconductorwidth=0.254 via.reliefentries=4 via.polygonreliefangle="90 Angle" via.airgapwidth=0.254
RoutingVias RoutingVias_GND [InNetClass('GND')] p1: holewidth=0.3 width=0.6 viastyle="Through Hole" minholewidth=0.2 minwidth=0.4 maxholewidth=0.3 maxwidth=0.6
RoutingVias RoutingVias_ALIMS [InNetClass('ALIMS')] p2: holewidth=0.3 width=0.6 viastyle="Through Hole" minholewidth=0.2 minwidth=0.4 maxholewidth=0.3 maxwidth=0.6
RoutingVias [All] p3: holewidth=0.2 width=0.4 viastyle="Through Hole" minholewidth=0.2 minwidth=0.4 maxholewidth=0.3 maxwidth=0.6
ShortCircuit ShortCircuit_LNK2 [InPadClass('LNK2')] p1: allowed=TRUE
ShortCircuit ShortCircuit_LNK1 [InPadClass('LNK1')] p2: allowed=TRUE
ShortCircuit [All] p3: allowed=FALSE
SilkToSilkClearance [All] p1: silktosilkclearance=0
SilkToSolderMaskClearance [IsPad] p1: minsilkscreentomaskgap=0 clearancetoexposedcopper=TRUE
SolderMaskExpansion [All] p1: expansion=0.05
Width Width_EMMC [InNetClass('NETC_EMMC')] p1: maxlimit=10 minlimit=0.09 preferedwidth=0.09
Width Width_BGA08_90U [InNetClass('BGA08')] p2: maxlimit=1 minlimit=0.09 preferedwidth=0.1 toplayer_prefwidth=0.09 midlayer1_minwidth=0.1 midlayer2_minwidth=0.1 midlayer3_minwidth=0.1 midlayer4_minwidth=0.1 bottomlayer_minwidth=0.1 minimp=50.000000 maximp=50.000000 favimp=50.000000
Width Width_SDMMC1 [InNetClass('NETC_SDMMC1')] p3: maxlimit=0.13 minlimit=0.09 preferedwidth=0.13
Width Width_RGMII_RXD [InNetClass('NETC_RGMII_RXD')] p4: maxlimit=0.13 minlimit=0.09 preferedwidth=0.13
Width Width_RGMII_TXD [InNetClass('NETC_RGMII_TXD')] p5: maxlimit=0.13 minlimit=0.09 preferedwidth=0.13
Width Width_ALIMS [InNetClass('ALIMS')] p6: maxlimit=10 minlimit=0.1 preferedwidth=0.3
Width Width_GND [InNetClass('GND')] p7: maxlimit=10 minlimit=0.085 preferedwidth=0.3 midlayer1_minwidth=0.1 midlayer2_minwidth=0.1 midlayer3_minwidth=0.1 midlayer4_minwidth=0.1 bottomlayer_minwidth=0.1 minimp=50.000000 maximp=50.000000 favimp=50.000000
Width [All] p8: maxlimit=10 minlimit=0.09 preferedwidth=0.1
15 further rules are at their usual default settings.

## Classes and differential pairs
net class NETC_CLK: SDMMC1_CK SDMMC1_CKIN
polygon class POLY_DIRECT_ALL: NETC906_2_L01_P192
net class NETC_BUS_SDMMC3: SDMMC3_CK SDMMC3_CMD SDMMC3_D0 SDMMC3_D1 SDMMC3_D2 SDMMC3_D3
net class NETC_BUS_SAI: SAI2_FSA SAI2_MCLKA SAI2_SCKA SAI2_SDA SAI2_SDB
net class NETC_BUS_LTDC: LTDC_B0 LTDC_B1 LTDC_B2 LTDC_B3 LTDC_B4 LTDC_B5 LTDC_B6 LTDC_B7 LTDC_CLK LTDC_DE LTDC_G0 LTDC_G1 LTDC_G2 LTDC_G3 LTDC_G4 LTDC_G5 LTDC_G6 LTDC_G7 LTDC_HSYNC LTDC_R0 LTDC_R1 LTDC_R2 LTDC_R3 LTDC_R4 LTDC_R5 LTDC_R6 LTDC_R7 LTDC_VSYNC
net class NETC_BUS_DCMI: DCMI_D0 DCMI_D1 DCMI_D2 DCMI_D3 DCMI_D4 DCMI_D5 DCMI_D6 DCMI_D7 DCMI_D8 DCMI_D9 DCMI_D10 DCMI_D11 DCMI_HSYNC DCMI_PIXCK DCMI_VSYNC
net class BGA08: ADC118_DAC1 ADC119_DAC2 ANA0 ANA1 BOOT0 BOOT1 BOOT2 CAN1_RX CAN1_TX CAN_FD_STBY DCMI_D0 DCMI_D2 DCMI_D3 DCMI_D4 DCMI_D5 DCMI_D7 DCMI_D8 DCMI_D9 DCMI_D10 DCMI_HSYNC DCMI_PIXCK DCMI_VSYNC DFSDM_CKOUT DFSDM_DATA1 DFSDM_DATA3 DFSDM_DATA5 DSI_CK_P DSI_D0_P DSI_D1_P DSI_RESET DSI_TE EMMC_SDIO2_D1 EMMC_SDIO2_D3 EMMC_SDIO2_D4 EMMC_SDIO2_D6 EMMC_SDIO2_D7 ETH_CLK125 ETH_MDINT ETH_RX_CLK ETH_RX_DV ETH_RXD1 ETH_RXD3 ETH_TX_EN ETH_TXD1 ETH_TXD3 GPIO7 HDMI_CEC I2C5_SCL I2C5_SDA JTCK_SWCLK JTDI JTDO_TRACESWO JTMS_SWDIO LCD_BL_CTRL LTDC_B0 LTDC_B2 LTDC_B3 LTDC_B4 LTDC_B6 LTDC_CLK LTDC_DE LTDC_G0 LTDC_G1 LTDC_G2 LTDC_G3 LTDC_G4 LTDC_G5 LTDC_G6 LTDC_G7 LTDC_HSYNC LTDC_R0 LTDC_R1 LTDC_R2 LTDC_R3 LTDC_R5 LTDC_R7 MCO1 MCO2 NAND_ALE NAND_D0 NAND_D2 NAND_D3 NAND_D4 NAND_D5 NAND_D6 NAND_D7 NAND_NCE NAND_NOE NAND_NWAIT NetC38_2 NetC75_2 NetC76_2 NetJP3_2 NetR29_1 NetR32_2 NetSB1_1 NetSB2_2 NJTRST NRST OTG_ID OTG_VBUS PA0_WKUP PA13 PA14 PF12 PMIC_WAKEUP QSPI_BK1_IO2 QSPI_BK1_IO3 QSPI_BK1_NCS QSPI_BK2_IO1 QSPI_BK2_IO2 QSPI_BK2_IO3 QSPI_BK2_NCS QSPI_CLK SAI2_MCLKA SAI2_MCLKB SAI2_SCKA SAI2_SDA SAI2_SDB SDMMC1_CDIR SDMMC1_CK SDMMC1_CKIN SDMMC1_CMD SDMMC1_D0 SDMMC1_D0DIR SDMMC1_D1 SDMMC1_D2 SDMMC1_D3 SDMMC1_D123DIR SDMMC2_CMD SDMMC3_CK SDMMC3_CMD SDMMC3_D0 SDMMC3_D1 SDMMC3_D2 SDMMC3_D3 SPDIF_RX SPDIF_TX SPI1_MISO SPI1_MOSI SPI1_NSS SPI1_SCK TIM2_CH4 TIM12_CH1 UART4_RX UART4_TX USART1_CK USART1_TX USART3_RTS USART3_RX USART3_TX USB1_P USB2_N USD_DETECT USD_LDO_SEL
net class GND: GND
net class ALIMS: 1V8 2V8 3V3 3V3_ST_LINK NetBT1_1 NetC40_2 VBUS_OTG VBUS_SW VDD VDD_CORE VDD_DDR VDD_SD VDD_USB VDDA VIN VREF_DDR VTT_DDR VUSB_ST_LINK
differential pair class DIFF_DDR: DDR_CLK DDR_DQS0 DDR_DQS1 DDR_DQS2 DDR_DQS3
differential pair class DIFF_DSI: DSI_CK DSI_D0 DSI_D1
differential pair class DIFF_USB: NewDifferentialPair1 STL_USB STLCN_USB USB1 USB2
net class NETC_DSI: DSI_CK_N DSI_CK_P DSI_D0_N DSI_D0_P DSI_D1_N DSI_D1_P
net class NETC_USB: STL_USB_N STL_USB_P STLCN_USB_N STLCN_USB_P USB1_N USB1_P USB2_N USB2_P
net class NETC_SDMMC1: SDMMC1_CDIR SDMMC1_CK SDMMC1_CKIN SDMMC1_CMD SDMMC1_D0 SDMMC1_D0DIR SDMMC1_D1 SDMMC1_D2 SDMMC1_D3 SDMMC1_D123DIR
net class NETC_RGMII_TXD: ETH_TX_EN ETH_TXD0 ETH_TXD1 ETH_TXD2 ETH_TXD3
net class NETC_RGMII_RXD: ETH_RX_DV ETH_RXD0 ETH_RXD1 ETH_RXD2 ETH_RXD3
net class NETC_BUS_NAND: DFSDM_DATA5 NAND_D0 NAND_D1 NAND_D2 NAND_D3 NAND_D4 NAND_D5 NAND_D6 NAND_D7 SAI2_FSB SAI2_MCLKB
net class NETC_BUS_QSPI_BK1: QSPI_BK1_IO0 QSPI_BK1_IO1 QSPI_BK1_IO2 QSPI_BK1_IO3 QSPI_BK1_NCS
net class NETC_BUS_QSPI_BK2: QSPI_BK2_IO0 QSPI_BK2_IO1 QSPI_BK2_IO2 QSPI_BK2_IO3 QSPI_BK2_NCS
net class NETC_BUS_JTAG: JTCK_SWCLK JTDI JTDO_TRACESWO JTMS_SWDIO NJTRST
net class NETC_EMMC: EMMC_SDIO2_D0 EMMC_SDIO2_D1 EMMC_SDIO2_D2 EMMC_SDIO2_D3 EMMC_SDIO2_D4 EMMC_SDIO2_D5 EMMC_SDIO2_D6 EMMC_SDIO2_D7 NetC39_1 NetR33_1 NetTP31_1 SDMMC2_CK SDMMC2_CMD
pad class LNK1: LNK1-1 LNK1-2
pad class LNK2: LNK2-1 LNK2-2
differential pair STLCN_USB: +STLCN_USB_P -STLCN_USB_N
differential pair DDR_CLK: +DDR_CLK_P -DDR_CLK_N
differential pair DDR_DQS0: +DDR_DQS0_P -DDR_DQS0_N
differential pair DDR_DQS1: +DDR_DQS1_P -DDR_DQS1_N
differential pair DDR_DQS2: +DDR_DQS2_P -DDR_DQS2_N
differential pair DDR_DQS3: +DDR_DQS3_P -DDR_DQS3_N
differential pair DSI_CK: +DSI_CK_P -DSI_CK_N
differential pair DSI_D0: +DSI_D0_P -DSI_D0_N
differential pair DSI_D1: +DSI_D1_P -DSI_D1_N
differential pair USB1: +USB1_P -USB1_N
differential pair USB2: +USB2_P -USB2_N
differential pair STL_USB: +STL_USB_P -STL_USB_N

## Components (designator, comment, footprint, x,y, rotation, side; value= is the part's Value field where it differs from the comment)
B1 "SW-PUSH-TS-02H-Black" SWI_JIUBABA_C-TS-02H-2-5-K-V-T_R_BLACK 6,111.525 r270 top locked
B2 "SW-PUSH-TS-02H-Blue" SWI_JIUBABA_C-TS-02H-2-5-B-V-T_R_BLUE 16,111.525 r90 top locked
B3 "SW-PUSH-TS-02H-Blue" SWI_JIUBABA_C-TS-02H-2-5-B-V-T_R_BLUE 26,111.525 r90 top locked
B4 "SW-PUSH-TS-02H-Blue" SWI_JIUBABA_C-TS-02H-2-5-B-V-T_R_BLUE 36,111.525 r270 top
BT1 "BATTERY Holder XCF-12" BAT_CHINA_XCF-12_SMD_2P 10.25,108.6 r270 bottom locked
C1 "220uF" CPOL_TAJ-C_2312_H2P6 44.1,113.7 r90 top
C2 "100nF" C0402 70.5,113.95 r270 top
C3 "1uF" C0603 58.275,112.7 r270 top
C4 "1uF" C0603 51.725,111.375 r270 top
C5 "10nF" C0402 33.675,109.75 r270 top
C6 "22uF" C0603 47.825,104.65 r180 top
C7 "22uF" C0603 51.725,104.825 r180 top
C8 "10uF" C0603 41.2,101.25 r90 top
C9 "10uF" C0603 48.55,102.85 r270 top
C10 "10uF" C0603 52.4,101.725 r270 top
C11 "4.7uF" C0402 54.85,100.7 r180 top
C12 "22uF" C0603 42.977,99.831 r0 top
C13 "4.7uF" C0402 54.85,99.1 r180 top
C14 "4.7uF" C0402 42.677,98.356 r0 top
C15 "4.7uF" C0402 54.875,97.975 r180 top
C16 "1uF" C0402 54.875,97.175 r180 top
C17 "4.7uF" C0402 54.875,96.375 r180 top
C18 "100nF" C0402 77.945,95.675 r180 top
C19 "1uF" C0402 54.875,95.575 r180 top
C20 "4.7uF" C0402 44.202,94.931 r270 top
C21 "4.7uF" C0402 42.802,94.906 r90 top
C22 "10uF" C0603 54.2,94.55 r180 top
C23 "10uF" C0603 54.2,93.3 r180 top
C24 "10uF" C0603 53.125,91.525 r90 top
C25 "10uF" C0603 49.075,90.55 r90 top
C26 "22uF" C0603 53.625,89.2 r180 top
C27 "22uF" C0603 46.3,89.2 r180 top
C28 "100nF" C0402 10.7,85.15 r0 top
C29 "100nF" C0402 15.35,85.15 r0 top
C30 "100nF" C0402 19.975,85.15 r0 top
C31 "100nF" C0402 23.35,85.145 r0 top
C32 "100nF" C0402 26.7,85.145 r0 top
C33 "6.8pF" C0402 22.1,78.9 r90 top
C34 "100nF" C0402 25.75,77.1 r90 top
C35 "6.8pF" C0402 19.8,77.4 r180 top
C36 "6.8pF" C0402 30.775,76.85 r180 top
C37 "6.8pF" C0402 32.525,76.85 r180 top
C38 "100nF" C0402 28.475,76.575 r0 top
C39 "2.2uF" C0603 51,60.525 r180 top
C40 "100nF" C0402 45.55,60.375 r180 top
C41 "100nF" C0402 51.25,59.375 r0 top
C42 "1uF" C0402 18.55,57.5 r180 top
C43 "1uF" C0402 45.55,56 r180 top
C44 "100nF" C0402 22.43,38.27 r90 top
C45 "100nF" C0402 22.43,36.49 r90 top
C46 "100nF" C0402 22.43,34.72 r270 top
C47 "100nF" C0402 22.39,31.2 r90 top
C48 "10uF" C0603 22.18,28.81 r270 top
C49 "100nF" C0402 24.53,18.22 r90 top
C50 "100nF" C0402 35.4,17.88 r90 top
C51 "100nF" C0402 24.52,16.28 r90 top
C52 "100nF" C0402 35.39,16.08 r90 top
C53 "100nF" C0402 24.52,14.47 r270 top
C54 "100nF" C0402 35.43,14 r90 top
C55 "1uF" C0603 70.325,13.975 r180 top
C56 "100pF" C0402 57.8,10.125 r180 top
C57 "4.7uF" C0603 74.125,8.525 r270 top
C58 "100nF" C0402 73,8.775 r90 top
C59 "10uF" C0603 24.38,6.4 r90 top
C60 "10nF" C0603 74.525,108.4 r0 bottom
C61 "1uF" C0603 76.9,105.65 r90 bottom
C62 "1uF" C0603 70.425,105.65 r90 bottom
C63 "100nF" C0402 78.075,105.4 r270 bottom
C64 "100nF" C0402 71.575,105.4 r270 bottom
C65 "100nF" C0402 24.53,10.83 r90 top
C66 "100nF" C0402 24.58,8.4 r90 top
C67 "1uF" C0402 54.85,99.9 r180 top
C68 "100nF" C0402 69.95,93.975 r0 bottom
C69 "100nF" C0402 61.225,91.15 r90 bottom
C70 "100nF" C0402 72.625,85.65 r270 bottom
C71 "100nF" C0402 65.775,82.775 r180 bottom
C72 "100nF" C0402 64.575,79.4 r270 bottom
C73 "10pF" C0402 68.875,77.45 r0 bottom
C74 "10pF" C0402 66.075,77.45 r180 bottom
C75 "100nF" C0402 30.275,70.275 r180 bottom
C76 "1uF" C0603 32.55,69.625 r180 bottom
C77 "1uF" C0402 35.54,65.58 r180 bottom
C78 "1uF" C0402 33.84,65.58 r180 bottom
C79 "1uF" C0402 32.14,65.58 r180 bottom
C80 "1uF" C0402 30.44,65.58 r180 bottom
C81 "2.2uF" C0603 61.625,64.325 r90 bottom
C82 "1uF" C0402 27.465,64.78 r0 bottom
C83 "1uF" C0402 35.54,64.18 r180 bottom
C84 "1uF" C0402 30.44,64.08 r180 bottom
C85 "1uF" C0402 33.84,63.98 r180 bottom
C86 "1uF" C0402 32.14,63.98 r180 bottom
C87 "1uF" C0402 28.94,63.18 r180 bottom
C88 "1uF" C0402 35.54,62.78 r180 bottom
C89 "1uF" C0402 33.84,62.38 r180 bottom
C90 "1uF" C0402 32.14,62.38 r180 bottom
C91 "1uF" C0402 30.44,62.28 r180 bottom
C92 "100nF" C0402 56,62.15 r0 bottom
C93 "1uF" C0402 23.65,61.53 r90 bottom
C94 "1uF" C0402 28.74,61.655 r0 bottom
C95 "2.2uF" C0603 61.975,60.875 r90 bottom
C96 "1uF" C0402 35.54,61.38 r180 bottom
C97 "100nF" C0402 22.575,60.725 r90 bottom
C98 "1uF" C0402 33.84,60.78 r180 bottom
C99 "1uF" C0402 32.14,60.78 r180 bottom
C100 "1uF" C0402 30.44,60.68 r180 bottom
C101 "1uF" C0402 28.74,60.68 r0 bottom
C102 "100nF" C0402 57.5,60.35 r0 bottom
C103 "1uF" C0402 35.54,59.98 r180 bottom
C104 "1uF" C0402 33.84,59.155 r180 bottom
C105 "1uF" C0402 32.14,59.155 r0 bottom
C106 "1uF" C0402 30.44,59.155 r0 bottom
C107 "1nF" C0402 28.74,59.155 r0 bottom
C108 "1nF" C0402 35.54,59.08 r0 bottom
C109 "1uF" C0402 26.64,58.405 r0 bottom
C110 "1uF" C0402 34.615,57.73 r180 bottom
C111 "1uF" C0402 40.95,57.25 r270 bottom
C112 "1uF" C0402 25.29,57.18 r270 bottom
C113 "100nF" C0402 22.465,56.905 r270 bottom
C114 "1uF" C0402 39.29,56.83 r180 bottom
C115 "100nF" C0402 18.56,54.83 r90 bottom
C116 "100nF" C0402 46.26,53.11 r90 bottom
C117 "100nF" C0402 32.84,36.38 r90 bottom
C118 "100nF" C0402 32.23,31.32 r270 bottom
C119 "100nF" C0402 32.23,29.58 r270 bottom
C120 "100nF" C0402 32.23,27.78 r90 bottom
C121 "100nF" C0402 22.66,26.78 r270 bottom
C122 "10uF" C0603 32.06,24.77 r90 bottom
C123 "100nF" C0402 21.93,19.19 r180 bottom
C124 "100nF" C0402 21.93,17.02 r180 bottom
C125 "100nF" C0402 21.93,13.84 r180 bottom
C126 "100nF" C0402 21.93,11.69 r180 bottom
C127 "100nF" C0402 19.29,9.66 r90 bottom
C128 "100nF" C0402 46.31,9.35 r90 bottom
C129 "100nF" C0402 21.93,9.6 r180 bottom
C130 "10uF" C0603 34.69,8.58 r270 bottom
C131 "100nF" C0402 33.08,7.07 r90 bottom
C132 "100nF" C0402 21.93,7.42 r180 bottom
C133 "22uF" C0603 40.3,4.5 r180 bottom
C134 "22uF" C0603 21.6,4.5 r0 bottom
C135 "100nF" C0402 35.59,3.64 r270 bottom
C136 "100nF" C0402 37.67,3.61 r270 bottom
C137 "100nF" C0402 33.44,3.61 r270 bottom
C138 "100nF" C0402 31.22,3.61 r270 bottom
C139 "100nF" C0402 29.13,3.61 r270 bottom
C140 "100nF" C0402 26.49,3.61 r270 bottom
C300 "10nF" C0402 18.3,79.2 r0 top
CN1 "DC10B" CON_DC-POWER-SOCKET_CLIFF_FC68149_DC10B 86,112 r0 top
CN2 "header 2 pins 2.54mm" CON_SAMTEC_TSW-102-07-G-S 60.2,106.4 r270 top
CN3 "Header 3x2" CON_SAMTEC_TSW-103-07-X-D 19.4,102.475 r270 top
CN4 "1050170001" CON_USBMICROB_MOLEX_105017-0001_H2P90 86,98 r90 top locked
CN5 "Header 4 pins" CON_SAMTEC_TSW-104-07-G-S 31.775,92.76 r270 top
CN6 "Header 4 pins" CON_SAMTEC_TSW-104-07-G-S 83.575,87.59 r270 top
CN7 "QTH-060-01-L-D-A" CON_SAMTEC_QTH-060-01-L-D-A 78,65 r270 bottom locked
CN8 "QTH-060-01-L-D-A" CON_SAMTEC_QTH-060-01-L-D-A 8,65 r270 bottom locked
CN9 "PJS008-2003-1" CON_MICROSD_YAMAICHI_PJS008-2003-1 86,10 r0 bottom locked
D1 "SMAJ5.0A" DIO_SMA_DO214-AC_1A_2K 60.675,113.775 r90 top
D2 "BAT60JFILM" DIO_SOD323 57.5,4.6 r270 top
D3 "BAT60JFILM" DIO_SOD323 76.4,101.83 r90 bottom
D4 "BAT60JFILM" DIO_SOD323 74.475,101.83 r90 bottom
D5 "BAT60JFILM" DIO_SOD323 75.225,87.7 r90 bottom
F1 "PTC FUSE 2.6A" PTC_BEL-FUSE_1812_0ZCG0260FF2C 66.2,112 r180 top
JP1 "Jumper_2.54mm" CON_SAMTEC_TSW-102-07-G-S 63.7,106.4 r270 top
JP2 "Jumper_2.54mm" CON_SAMTEC_TSW-102-07-G-S 67.2,106.4 r270 top
JP3 "Header 3 pins" CON_SAMTEC_TSW-103-07-F-S 23.8,102.475 r90 top
JP4 "Header 3 pins" CON_SAMTEC_TSW-103-07-F-S 27.3,102.475 r90 top locked
JP5 "Header 3 pins" CON_SAMTEC_TSW-103-07-F-S 30.8,102.475 r90 top
JP6 "Jumper_2.54mm" CON_SAMTEC_TSW-102-07-G-S 6.475,90.225 r90 top
JP7 "Jumper_2.54mm" CON_SAMTEC_TSW-102-07-G-S 11.15,90.225 r90 top
JP8 "Jumper_2.54mm" CON_SAMTEC_TSW-102-07-G-S 15.8,90.225 r90 top
JP9 "Jumper_2.54mm" CON_SAMTEC_TSW-102-07-G-S 20.45,90.225 r90 top
JP10 "Jumper_2.54mm" CON_SAMTEC_TSW-102-07-G-S 27.15,90.22 r90 top
JP11 "Jumper_2.54mm" CON_SAMTEC_TSW-102-07-G-S 23.9,90.2 r90 top
L1 "1uH" IND_2520_TOKO_DFE252012P 46.625,102.425 r90 top
L2 "1uH" IND_2520_TOKO_DFE252012P 50.475,102.425 r90 top
L3 "1uH" IND_2520_TOKO_DFE252012P 43.4,101.775 r0 top
L4 "1uH" IND_2520_TOKO_DFE252012P 51.175,90.975 r270 top
L5 "1uH" IND_2520_TOKO_DFE252012P 46.7,91.3 r180 top
LD1 "LED_green_1" LED_0603_GREEN 46.75,115.925 r90 top value=GREEN
LD2 "LED_red_1" LED_0603_RED 13.525,110.1 r270 top value=RED
LD3 "LED_green_1" LED_0603_GREEN 23.525,110.1 r270 top value=GREEN
LD4 "LED_orange" LED_0603_ORANGE_H0P4 32,110.05 r270 top value=ORANGE
LD5 "​reference from jiubaba" LED_0603_SMD-B_BLUE_H0P4 30.1,110 r270 top value=BLUE
LD6 "LD_BICOLOR_CMS" LED_BI-GR_HSMF-A201-A00J1 82.325,104.725 r90 top locked
LE1 "4.7uH" L0603 35.825,76.275 r0 bottom
LNK1 "link_200" LINK200 41.825,59.775 r90 top
LNK2 "link_200" LINK200 47.775,45.675 r135 top
M1 "IP4856CX25/C_Module_REV" MOD_SD-CARD_8X8_MB1256 63.275,8.125 r0 top value=MB1256
MIRE1 ".designator" MIRE_PLACE_SMD_0P8MM 2.2,117.875 r0 top
MIRE2 ".designator" MIRE_PLACE_SMD_0P8MM 68.875,117.375 r0 top
MIRE3 ".designator" MIRE_PLACE_SMD_0P8MM 3.7,3.35 r0 top
MIRE4 ".designator" MIRE_PLACE_SMD_0P8MM 20.125,116.775 r180 bottom
MIRE5 ".designator" MIRE_PLACE_SMD_0P8MM 66.6,116.4 r180 bottom
MIRE6 ".designator" MIRE_PLACE_SMD_0P8MM 4.05,3.3 r180 bottom
R1 "39R 1%" R0402 55.025,114.35 r0 top
R2 "330R" R0402 46.75,113.675 r270 top
R3 "1K" R0402 13.525,112.325 r270 top
R4 "330R" R0402 23.525,112.325 r90 top
R5 "Resistor" R0402 30.1,112.3 r270 top value=680R
R6 "Resistor" R0402 32,112.3 r270 top value=680R
R7 "0R_0603_ULO" R0603 56.875,111.3 r270 top
R8 "10K" R0402 8.4,109.75 r90 top
R9 "100R" R0402 18.4,109.75 r90 top
R10 "100R" R0402 28.4,109.75 r90 top
R11 "1K" R0402 12.3,104.15 r270 top
R12 "1K" R0402 13.575,104.15 r270 top
R13 "1K" R0402 14.825,104.15 r270 top
R14 "100K" R0402 80.275,100.05 r270 top
R15 "0R" R0402 29.5,97.025 r90 top
R16 "0R" R0402 11.15,86.475 r90 top
R17 "0R" R0402 15.8,86.475 r90 top
R18 "0R" R0402 20.425,86.475 r90 top
R19 "0R" R0402 23.8,86.47 r90 top
R20 "0R" R0402 27.15,86.47 r90 top
R21 "0R" R0402 11.15,83.825 r90 top
R22 "0R" R0402 15.8,83.825 r90 top
R23 "0R" R0402 20.425,83.825 r90 top
R24 "0R" R0402 23.8,83.82 r90 top
R25 "0R" R0402 27.15,83.82 r90 top
R26 "0R" R0402 19.8,76.5 r0 top
R27 "0R" R0402 28.475,77.475 r180 top
R28 "0R" R0402 31.1,75.525 r90 top
R29 "0R" R0402 32.2,75.525 r90 top
R30 "1K5" R0402 45.55,73.4 r0 top
R31 "1K5" R0402 45.55,72.325 r0 top
R32 "3K" R0402 18.55,56.475 r0 top
R33 "10K" R0402 61.475,55.7 r0 top
R34 "1K5" R0402 15.775,54.8 r270 top
R35 "1K5" R0402 16.85,54.8 r270 top
R36 "240" R0402 22.36,32.97 r90 top
R37 "10K" R0402 61.725,13.7 r270 top
R38 "10K" R0402 62.775,13.7 r90 top
R39 "10K" R0402 63.775,13.7 r90 top
R40 "10K" R0402 64.825,13.7 r270 top
R41 "10K" R0402 57.8,11.125 r0 top
R42 "0R" R0402 57.8,9.125 r0 top
R43 "10K" R0402 57.8,8.075 r180 top
R44 "10K" R0402 57.8,7 r0 top
R45 "0R" R0402 55.7,6.1 r0 top
R46 "10K" R0402 55.7,4.9 r180 top
R47 "10K" R0402 55.7,3.7 r0 top
R48 "10K" R0402 62.65,2.45 r90 top
R49 "10K" R0402 63.925,2.45 r270 top
R50 "0R_0603_ULO" R0603 48.45,104.525 r270 bottom
R51 "1K5" R0402 75.3,94.725 r270 bottom
R52 "10K" R0402 81.575,92.1 r90 bottom
R53 "1K5" R0402 41.075,79.025 r270 bottom
R54 "0R" R0402 61.475,54.575 r180 top
R55 "240" R0402 24.45,12.68 r90 top
R56 "0R" R0402 83.7,105.925 r270 bottom
R57 "330R" R0402 80.825,105.475 r180 bottom
R58 "330R" R0402 80.825,103.975 r180 bottom
R59 "0R_0603_ULO" R0603 39.75,101 r0 bottom
R60 "0R_0603_ULO" R0603 56.525,102.975 r270 bottom
R61 "0R_0603_ULO" R0603 52.475,100.4 r270 bottom
R62 "0R_0603_ULO" R0603 51.05,100.4 r270 bottom
R63 "0R_0603_ULO" R0603 39.75,97.475 r0 bottom
R64 "0R_0603_ULO" R0603 39.75,93.825 r270 bottom
R65 "36K" R0402 80.525,92.1 r90 bottom
R66 "1K" R0402 59.775,91.15 r270 bottom
R67 "100R" R0402 81.575,90.325 r270 bottom
R68 "0R_0603_ULO" R0603 56.375,91.95 r180 bottom
R69 "4K7" R0402 75.125,89.975 r0 bottom
R70 "2K7" R0402 73.75,89.65 r90 bottom
R71 "0R" R0402 72.7,89.65 r90 bottom
R72 "0R_0603_ULO" R0603 48.7,88.8 r90 bottom
R73 "100K" R0402 60.825,89.2 r0 bottom
R74 "100K" R0402 73.025,87.7 r0 bottom
R75 "0R_0603_ULO" R0603 59.027,85.05 r270 bottom
R76 "0R_0603_ULO" R0603 57.527,85.05 r270 bottom
R77 "0R_0603_ULO" R0603 56.002,85.05 r270 bottom
R78 "0R_0603_ULO" R0603 54.477,85.05 r270 bottom
R79 "0R_0603_ULO" R0603 52.4,85.05 r90 bottom
R80 "0R_0603_ULO" R0603 50.925,85.05 r270 bottom
R81 "0R_0603_ULO" R0603 45.9,85.075 r270 bottom
R82 "0R_0603_ULO" R0603 44.202,85.05 r270 bottom
R83 "0R_0603_ULO" R0603 42.327,85.05 r270 bottom
R84 "0R_0603_ULO" R0603 40.827,85.05 r270 bottom
R85 "0R_0603_ULO" R0603 39.302,85.05 r270 bottom
R86 "0R_0603_ULO" R0603 37.777,85.05 r270 bottom
R87 "0R_0603_ULO" R0603 36.052,85.05 r270 bottom
R88 "10K" R0402 69.975,82.35 r270 bottom
R89 "10K" R0402 68.925,82.35 r270 bottom
R90 "4K7" R0402 64.125,82.275 r90 bottom
R91 "4K7" R0402 63.05,82.275 r90 bottom
R92 "100K" R0402 63.6,79.4 r270 bottom
R93 "1K5" R0402 40,79.025 r270 bottom
R94 "0R" R0402 36.875,78.6 r180 bottom
R95 "0R" R0402 34.75,78.6 r0 bottom
R96 "0R" R0402 31.885,71.2 r90 bottom
R97 "10K" R0402 45.8,67.775 r0 bottom
R98 "0R" R0402 25.01,63.575 r0 bottom
R99 "0R" R0402 25.45,62.525 r0 bottom
R100 "10K" R0402 60.775,61.05 r270 bottom
R101 "0R" R0402 44.125,60.225 r0 bottom
R102 "240 1%" R0402 33.13,51.21 r0 bottom value=240
R103 "10K" R0402 43.26,37.12 r90 bottom
R104 "56R" R0402 23.64,19.72 r180 bottom
R105 "56R" R0402 23.64,18.64 r180 bottom
R106 "56R" R0402 23.64,17.57 r180 bottom
R107 "56R" R0402 23.64,16.5 r180 bottom
R108 "10K" R0402 24.54,15.44 r180 bottom
R109 "56R" R0402 23.64,14.37 r180 bottom
R110 "56R" R0402 23.64,13.29 r180 bottom
R111 "10K" R0402 68.2,12.525 r180 bottom
R112 "56R" R0402 23.64,12.22 r180 bottom
R113 "10K" R0402 68.2,11.425 r180 bottom
R114 "56R" R0402 23.64,11.15 r180 bottom
R115 "10K" R0402 68.2,10.325 r180 bottom
R116 "56R" R0402 23.64,10.09 r180 bottom
R117 "56R" R0402 23.64,9.02 r180 bottom
R118 "100R" R0402 26.89,8.68 r0 bottom
R119 "56R" R0402 23.64,7.94 r180 bottom
R120 "56R" R0402 23.64,6.85 r180 bottom
R121 "10K" R0402 68.2,5.925 r180 bottom
R122 "56R" R0402 38.23,5.32 r270 bottom
R123 "56R" R0402 37.19,5.32 r270 bottom
R124 "56R" R0402 36.12,5.32 r270 bottom
R125 "56R" R0402 35.07,5.32 r270 bottom
R126 "56R" R0402 34.03,5.32 r270 bottom
R127 "56R" R0402 32.87,5.32 r270 bottom
R128 "56R" R0402 31.82,5.32 r270 bottom
R129 "56R" R0402 30.75,5.32 r270 bottom
R130 "56R" R0402 29.68,5.32 r270 bottom
R131 "56R" R0402 28.62,5.32 r270 bottom
R132 "56R" R0402 27.04,5.32 r270 bottom
R133 "56R" R0402 26.02,5.32 r270 bottom
R134 "56R" R0402 24.94,5.32 r270 bottom
R135 "10K" R0402 68.2,4.825 r180 bottom
R300 "Resistor" R0402 18.3,78.3 r0 top value=10R
R302 "10K" R0402 18.5,77 r90 top
R303 "1K" R0402 21.1,77 r90 top
R900 "10K" R0402 55.6,60.9 r0 bottom
R901 "10K" R0402 58,63.4 r180 bottom
SB1 "SB_ON" SOLDER-BRIDGE_R0603-0R 22.1,95.329 r270 top
SB2 "SB_OFF" SOLDER-BRIDGE_R0603-0R 18.8,95.325 r90 top
SB3 "SB_OFF" SOLDER-BRIDGE_R0603-0R 20.425,95.325 r90 top
SB4 "SB_ON" SOLDER-BRIDGE_R0603-0R 17.2,95.3 r270 top
SB5 "SB_ON" SOLDER-BRIDGE_R0603-0R 8.825,88.75 r270 top
SB6 "SB_ON" SOLDER-BRIDGE_R0603-0R 13.475,88.75 r270 top
SB7 "SB_ON" SOLDER-BRIDGE_R0603-0R 18.125,88.75 r270 top
SB8 "SB_ON" SOLDER-BRIDGE_R0603-0R 67.3,88.2 r0 top
SB9 "SB_ON" SOLDER-BRIDGE_R0603-0R 73.55,5.75 r0 top
SW1 "CT218-4LPSTRI" SWI_CTS_CTS218-4LP 12.92,98.535 r180 top
T1 "BSR14" NPN_SOT23 79.275,90.225 r180 bottom
TP1 "TP" TP_SMD_1MM 22.05,109.35 r90 top
TP2 "TP" TP_SMD_1MM 27.05,97.2 r90 top
TP3 "TP" TP_SMD_1MM 14.45,78.825 r90 top
TP4 "TP" TP_SMD_1MM 28.35,78.8 r90 top
TP5 "TP" TP_SMD_1MM 33.825,75.775 r0 top
TP6 "TP" TP_SMD_1MM 4.9,75.55 r0 top
TP7 "TP" TP_SMD_1MM 4.9,73.925 r0 top
TP8 "TP" TP_SMD_1MM 4.9,72.25 r0 top
TP9 "TP" TP_SMD_1MM 4.9,70.55 r180 top
TP12 "TP 0.6" TP_SMD_0-6MM 20.125,55.95 r270 top
TP13 "TP" TP_SMD_1MM 11.1,51.75 r90 top
TP14 "TP" TP_SMD_1MM 9.575,50.75 r180 top
TP15 "TP" TP_SMD_1MM 11.1,49.75 r180 top
TP16 "TP 0.6" TP_SMD_0-6MM 31.83,49.9 r0 top
TP17 "TP 0.6" TP_SMD_0-6MM 33.41,49.74 r0 top
TP18 "TP" TP_SMD_1MM 9.575,48.75 r180 top
TP19 "TP" TP_SMD_1MM 11.1,47.75 r180 top
TP20 "TP 0.3" TP_SMD_0-3MM 35.14,30.63 r0 top
TP21 "TP 0.3" TP_SMD_0-3MM 35.54,30.33 r0 top
TP22 "TP 0.6" TP_SMD_0-6MM 36.85,27.89 r0 top
TP23 "TP 0.6" TP_SMD_0-6MM 37.65,27.22 r0 top
TP24 "TP 0.6" TP_SMD_0-6MM 37.87,19.81 r0 top
TP25 "TP 0.6" TP_SMD_0-6MM 37.84,18.6 r0 top
TP26 "TP 0.6" TP_SMD_0-6MM 43.99,16.41 r0 top
TP27 "TP 0.3" TP_SMD_0-3MM 40.44,16.6 r0 top
TP28 "TP 0.3" TP_SMD_0-3MM 40.44,16.1 r0 top
TP29 "TP" TP_SMD_1MM 65.925,2.475 r0 top
TP30 "TP" TP_SMD_1MM 34.05,71.575 r180 bottom
TP31 "TP" TP_SMD_1MM 59.775,59.15 r90 bottom
TP32 "TP 0.6" TP_SMD_0-6MM 32.5,33.63 r0 bottom
TP33 "TP 0.6" TP_SMD_0-6MM 28.27,33.22 r0 bottom
TP34 "TP 0.6" TP_SMD_0-6MM 28.05,31.58 r0 bottom
TP35 "TP 0.6" TP_SMD_0-6MM 28.54,29.91 r0 bottom
TP36 "TP 0.6" TP_SMD_0-6MM 28.66,28.04 r0 bottom
TP37 "TP 0.6" TP_SMD_0-6MM 29.42,12.29 r0 bottom
U1 "STEF05LPUR" ICC_DFN10-EPAD_3X3_P050 54.275,112 r0 top
U2 "ESDALC6V1-1U2" ESD_ST0201 6.188,108.2 r180 top
U3 "STPMU1A" ICC_WFQFN44-EPAD_5X6_P040 48.879,96.286 r90 top locked
U4 "STM32MP157CAA3_Socket" ICC_LFBGA448_18X18_STM32MP157BAA3_P080__SOCKET_IE_CS1627194MF 32.59,62.38 r270 top locked
U5 "THGBMNG5D1LBAIL" ICC_P-WFBGA153_13X11P5_P050 59.025,62.4 r0 top locked
U6 "NT5CC256M16ER-EK_interposer" "ICC_FBGA96_9X13_8X14_P080_DI _INTERPOSER" 27.79,32.18 r0 top locked
U7 "NT5CC256M16ER-EK" ICC_FBGA96_9X13_8X14_P080_DI 30.04,12.32 r180 top locked
U8 "USBLC6-2P6" ESD_SOT666 77.945,95.675 r270 bottom
U9 "LD3985M33R" REG_SOT23-5L 74.125,105.9 r90 bottom
U10 "STM32F103CBT6" ICC_LQFP48_7X7_P050 66.975,88.45 r180 bottom locked
X2 "NX2012SA-32.768KHz" CRY_NX2012SA_2P 31.65,78.2 r0 top value=32.768kHz
X3 "NX3225GD-8.00M" CRY_NX3225GD_2P 67.475,79.475 r0 bottom
X6 "OSCILLATOR_4_PINS" CRY_NZ2016SH_4P 20.4,78.8 r0 top value="NZ2016SH 24MHz"

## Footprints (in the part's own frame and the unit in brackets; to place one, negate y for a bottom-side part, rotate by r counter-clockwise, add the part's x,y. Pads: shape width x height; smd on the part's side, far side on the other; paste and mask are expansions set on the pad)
BAT_CHINA_XCF-12_SMD_2P [mm]
  rect 4.4x2.3 smd mask+0.05: 1(8,0)
  rect 4x2.3 smd mask+0.05: 2(-8,0)
  round 0.5 hole 1.2 unplated mask+0.05: NPTH1(-3.6,0) NPTH2(3.9,0)
  silkscreen extent -9.03,-7.5 9.62,7.5, body extent -8.88,-7.52 9.62,7.5, height 4.04
C0402 [mm]
  rect 0.51x0.56 smd mask+0.05: 1(-0.45,0) 2(0.45,0)
  silkscreen extent 0,-0.3 0,0.3, body extent -0.5,-0.3 0.5,0.3, height 0.4
C0603 [mm]
  rect 0.64x0.89 smd mask+0.05: 1(-0.7,0) 2(0.7,0)
  silkscreen extent -1.05,-0.55 1.02,0.55, body extent -0.9,-0.5 0.9,0.5, height 1.4
CON_DC-POWER-SOCKET_CLIFF_FC68149_DC10B [mm]
  oval 2.2x4.6 hole 1 slot 3.5 at 90 deg mask+0.05: 1(-13.55,0) 3(-7.4,0)
  oval 4.6x2.2 hole 1 slot 3.5 at 0 deg mask+0.05: 2(-10.7,5)
  silkscreen extent -14.2,-4.6 0,4.6, body extent -14.3,-4.6 0.2,5.27, height 11
CON_MICROSD_YAMAICHI_PJS008-2003-1 [mm] "WITH POSITIONNING PINS"
  rect 1.6x0.8 smd paste+0 mask+0.05: 1(-15.6,-2.525) 2(-15.6,-1.425) 3(-15.6,-0.325) 4(-15.6,0.775) 5(-15.6,1.875) 6(-15.6,2.975) 7(-15.6,4.075) 8(-15.6,5.175) 9(-15.6,6.325)
  rect 1.4x1.95 smd paste+0 mask+0.05: 10(-5.4,7.225)
  rect 3.5x1.5 smd paste+0 mask+0.05: 11(-2.45,7.45)
  rect 3.5x1.4 smd paste+0 mask+0.05: 12(-2.45,-7.5)
  rect 3.5x1.6 smd paste+0 mask+0.05: 13(-13.45,-7.4)
  rect 3.1x1.2 smd paste+0 mask+0.05: 14(-13.95,7.6)
  round 0 hole 0.65 unplated mask+0.05: NPTH1(-9.8,-4)
  round 0 hole 0.7 unplated mask+0.05: NPTH2(-9.8,3.55)
  silkscreen extent -15.32,-7.25 5.65,7.25, body extent -15.25,-7.25 -0.45,7.42, height 2
CON_SAMTEC_QTH-060-01-L-D-A [mm]
  rect 0.3x1.45 smd mask+0.05: 1(-17.25,3.1) 2(-17.25,-3.1) 3(-16.75,3.1) 4(-16.75,-3.1) 5(-16.25,3.1) 6(-16.25,-3.1) 7(-15.75,3.1) 8(-15.75,-3.1) 9(-15.25,3.1) 10(-15.25,-3.1) 11(-14.75,3.1) 12(-14.75,-3.1) 13(-14.25,3.1) 14(-14.25,-3.1) 15(-13.75,3.1) 16(-13.75,-3.1) 17(-13.25,3.1) 18(-13.25,-3.1) 19(-12.75,3.1) 20(-12.75,-3.1) 21(-12.25,3.1) 22(-12.25,-3.1) 23(-11.75,3.1) 24(-11.75,-3.1) 25(-11.25,3.1) 26(-11.25,-3.1) 27(-10.75,3.1) 28(-10.75,-3.1) 29(-10.25,3.1) 30(-10.25,-3.1) 31(-9.75,3.1) 32(-9.75,-3.1) 33(-9.25,3.1) 34(-9.25,-3.1) 35(-8.75,3.1) 36(-8.75,-3.1) 37(-8.25,3.1) 38(-8.25,-3.1) 39(-7.75,3.1) 40(-7.75,-3.1) 41(-7.25,3.1) 42(-7.25,-3.1) 43(-6.75,3.1) 44(-6.75,-3.1) 45(-6.25,3.1) 46(-6.25,-3.1) 47(-5.75,3.1) 48(-5.75,-3.1) 49(-5.25,3.1) 50(-5.25,-3.1) 51(-4.75,3.1) 52(-4.75,-3.1) 53(-4.25,3.1) 54(-4.25,-3.1) 55(-3.75,3.1) 56(-3.75,-3.1) 57(-3.25,3.1) 58(-3.25,-3.1) 59(-2.75,3.1) 60(-2.75,-3.1) 61(2.75,3.1) 62(2.75,-3.1) 63(3.25,3.1) 64(3.25,-3.1) 65(3.75,3.1) 66(3.75,-3.1) 67(4.25,3.1) 68(4.25,-3.1) 69(4.75,3.1) 70(4.75,-3.1) 71(5.25,3.1) 72(5.25,-3.1) 73(5.75,3.1) 74(5.75,-3.1) 75(6.25,3.1) 76(6.25,-3.1) 77(6.75,3.1) 78(6.75,-3.1) 79(7.25,3.1) 80(7.25,-3.1) 81(7.75,3.1) 82(7.75,-3.1) 83(8.25,3.1) 84(8.25,-3.1) 85(8.75,3.1) 86(8.75,-3.1) 87(9.25,3.1) 88(9.25,-3.1) 89(9.75,3.1) 90(9.75,-3.1) 91(10.25,3.1) 92(10.25,-3.1) 93(10.75,3.1) 94(10.75,-3.1) 95(11.25,3.1) 96(11.25,-3.1) 97(11.75,3.1) 98(11.75,-3.1) 99(12.25,3.1) 100(12.25,-3.1) 101(12.75,3.1) 102(12.75,-3.1) 103(13.25,3.1) 104(13.25,-3.1) 105(13.75,3.1) 106(13.75,-3.1) 107(14.25,3.1) 108(14.25,-3.1) 109(14.75,3.1) 110(14.75,-3.1) 111(15.25,3.1) 112(15.25,-3.1) 113(15.75,3.1) 114(15.75,-3.1) 115(16.25,3.1) 116(16.25,-3.1) 117(16.75,3.1) 118(16.75,-3.1) 119(17.25,3.1) 120(17.25,-3.1)
  rect 2.54x0.64 smd mask+0.05: 121(-18.447,0) 124(-1.557,0) 125(1.557,0) 128(18.447,0)
  rect 4.7x0.64 smd mask+0.05: 122(-13.177,0) 123(-6.827,0) 126(6.827,0) 127(13.177,0)
  round 0.5 hole 1.1 unplated mask+0.1: FIX1(-19.24,2.03) FIX2(19.24,2.03)
  silkscreen extent -20.15,-3.5 20.15,3.5, body extent -20.21,-3.56 20.21,3.56, height 5
CON_SAMTEC_TSW-102-07-G-S [mm]
  rect 1.85x1.85 / inner round 1.85 / far side rect 1.85x1.85 hole 1 mask+0.05: 1(-1.27,0)
  round 1.85 hole 1 mask+0.05: 2(1.27,0)
  silkscreen extent -2.58,-1.3 2.58,1.3, body extent -2.67,-1.3 2.58,1.3, height 8.38
CON_SAMTEC_TSW-103-07-F-S [mm]
  rect 1.85x1.85 / inner round 1.85 / far side rect 1.85x1.85 hole 1 mask+0.05: 1(-2.54,0)
  round 1.85 hole 1 mask+0.05: 2(0,0) 3(2.54,0)
  silkscreen extent -3.85,-1.3 3.85,1.3, body extent -3.91,-1.37 3.91,1.37, height 8.38
CON_SAMTEC_TSW-103-07-X-D [mm]
  rect 1.85x1.85 / inner round 1.85 / far side rect 1.85x1.85 hole 1 mask+0.05: 1(-2.54,-1.27)
  round 1.85 hole 1 mask+0.05: 2(-2.54,1.27) 3(0,-1.27) 4(0,1.27) 5(2.54,-1.27) 6(2.54,1.27)
  silkscreen extent -3.81,-2.54 3.81,2.54, body extent -3.81,-2.54 3.81,2.54, height 8.38
CON_SAMTEC_TSW-104-07-G-S [mm]
  rect 1.85x1.85 / inner round 1.85 / far side rect 1.85x1.85 hole 1 mask+0.05: 1(-3.81,0)
  round 1.85 hole 1 mask+0.05: 2(-1.27,0) 3(1.27,0) 4(3.81,0)
  silkscreen extent -5.12,-1.3 5.12,1.3, body extent -5.21,-1.37 5.18,1.37, height 8.38
CON_USBMICROB_MOLEX_105017-0001_H2P90 [mm]
  rect 0.4x1.35 smd mask+0.05: 1(-1.3,4.15) 2(-0.65,4.15) 3(0,4.15) 4(0.65,4.15) 5(1.3,4.15)
  round 1.5 hole 0.9 mask+0.05: 6(-2.5,4.15) 7(2.5,4.15)
  oval 1.2x1.9 hole 0.6 slot 1.3 at 90 deg mask+0.05: 8(3.5,1.45) 9(-3.5,1.45)
  rect 1.5x1.9 smd mask+0.05: 10(-1,1.45) 11(1,1.45)
  Top Layer region: -3.5,2.4 -2.3,2.4 -2.3,0.5 -3.5,0.5 -3.5,2.4
  Top Layer region: 2.3,2.4 3.5,2.4 3.5,0.5 2.3,0.5 2.3,2.4
  silkscreen extent -4,-0.7 4,4.6, body extent -4.1,-1.15 4.1,4.66, height 2.9
CPOL_TAJ-C_2312_H2P6 [mm]
  rect 2.2x2.6 smd mask+0.05: 1(-2.3,0) 2(2.3,0)
  silkscreen extent -3.6,-1.85 3.1,1.85, body extent -3.1,-1.7 3.1,1.7, height 2.8
CRY_NX2012SA_2P [mm]
  rect 1x1.25 smd mask+0.05: 1(-0.75,0) 2(0.75,0)
  silkscreen extent -1.05,-0.75 1.05,0.75, body extent -1.05,-0.63 1.05,0.63, height 0.6
CRY_NX3225GD_2P [mm]
  rect 1.5x2.7 smd mask+0.05: 1(-0.95,0) 2(0.95,0)
  silkscreen extent -0.1,-1.3 0.1,1.3, body extent -1.65,-1.3 1.65,1.3, height 1
CRY_NZ2016SH_4P [mm] "MCD-01627"
  rect 0.8x0.7 smd mask+0.05: 1(-0.65,-0.5) 2(0.65,-0.5) 3(0.65,0.5) 4(-0.65,0.5)
  silkscreen extent -1.17,-0.97 1.05,0.85, body extent -1.05,-0.85 1.05,0.85, height 0.71
DIO_SMA_DO214-AC_1A_2K [mm]
  rect 2.15x2.5 smd mask+0.05: 1(1.775,0) 2(-1.775,0)
  silkscreen extent -2.25,-1.4 2.25,1.4, body extent -2.75,-1.4 2.75,1.4, height 2.6
DIO_SOD323 [mm]
  rect 1.06x0.54 smd mask+0.05: 1(-1.07,0) 2(1.07,0)
  silkscreen extent -0.9,-0.72 0.9,0.72, body extent -1.3,-0.78 1.3,0.78, height 1.17
ESD_SOT666 [mm]
  rect 0.3x0.99 smd mask+0.05: 1(-0.5,-0.805) 2(0,-0.805) 3(0.5,-0.805) 4(0.5,0.805) 5(0,0.805) 6(-0.5,0.805)
  silkscreen extent -0.85,-0.65 0.85,0.65, body extent -0.85,-0.8 0.85,0.8, height 0.6
ESD_ST0201 [mm]
  rect 0.425x0.33 smd mask+0.05: 1(-0.312,0) 2(0.312,0)
  silkscreen extent -0.55,-0.3 0.33,0.3, body extent -0.34,-0.18 0.34,0.18, height 0.34
ICC_DFN10-EPAD_3X3_P050 [mm]
  rect 0.3x0.5 smd mask+0.05: 1(-1,-1.325) 2(-0.5,-1.325) 3(0,-1.325) 4(0.5,-1.325) 5(1,-1.325) 6(1,1.325) 7(0.5,1.325) 8(0,1.325) 9(-0.5,1.325) 10(-1,1.325)
  rect 3.1x1.75 smd mask+0.05: EP(0,0)
  silkscreen extent -1.68,-1.55 1.68,1.55, body extent -1.55,-1.56 1.55,1.56, height 1
ICC_FBGA96_9X13_8X14_P080_DI [mm]
  round 0.4 smd mask+0.05: A1(-3.2,6) A2(-2.4,6) A3(-1.6,6) A7(1.6,6) A8(2.4,6) A9(3.2,6) B1(-3.2,5.2) B2(-2.4,5.2) B3(-1.6,5.2) B7(1.6,5.2) B8(2.4,5.2) B9(3.2,5.2) C1(-3.2,4.4) C2(-2.4,4.4) C3(-1.6,4.4) C7(1.6,4.4) C8(2.4,4.4) C9(3.2,4.4) D1(-3.2,3.6) D2(-2.4,3.6) D3(-1.6,3.6) D7(1.6,3.6) D8(2.4,3.6) D9(3.2,3.6) E1(-3.2,2.8) E2(-2.4,2.8) E3(-1.6,2.8) E7(1.6,2.8) E8(2.4,2.8) E9(3.2,2.8) F1(-3.2,2) F2(-2.4,2) F3(-1.6,2) F7(1.6,2) F8(2.4,2) F9(3.2,2) G1(-3.2,1.2) G2(-2.4,1.2) G3(-1.6,1.2) G7(1.6,1.2) G8(2.4,1.2) G9(3.2,1.2) H1(-3.2,0.4) H2(-2.4,0.4) H3(-1.6,0.4) H7(1.6,0.4) H8(2.4,0.4) H9(3.2,0.4) J1(-3.2,-0.4) J2(-2.4,-0.4) J3(-1.6,-0.4) J7(1.6,-0.4) J8(2.4,-0.4) J9(3.2,-0.4) K1(-3.2,-1.2) K2(-2.4,-1.2) K3(-1.6,-1.2) K7(1.6,-1.2) K8(2.4,-1.2) K9(3.2,-1.2) L1(-3.2,-2) L2(-2.4,-2) L3(-1.6,-2) L7(1.6,-2) L8(2.4,-2) L9(3.2,-2) M1(-3.2,-2.8) M2(-2.4,-2.8) M3(-1.6,-2.8) M7(1.6,-2.8) M8(2.4,-2.8) M9(3.2,-2.8) N1(-3.2,-3.6) N2(-2.4,-3.6) N3(-1.6,-3.6) N7(1.6,-3.6) N8(2.4,-3.6) N9(3.2,-3.6) P1(-3.2,-4.4) P2(-2.4,-4.4) P3(-1.6,-4.4) P7(1.6,-4.4) P8(2.4,-4.4) P9(3.2,-4.4) R1(-3.2,-5.2) R2(-2.4,-5.2) R3(-1.6,-5.2) R7(1.6,-5.2) R8(2.4,-5.2) R9(3.2,-5.2) T1(-3.2,-6) T2(-2.4,-6) T3(-1.6,-6) T7(1.6,-6) T8(2.4,-6) T9(3.2,-6)
  silkscreen extent -4.55,-7.05 4.55,7.05, body extent -4.55,-7.05 4.55,7.05, height 1.2
"ICC_FBGA96_9X13_8X14_P080_DI _INTERPOSER" [mm] "INTERPOSER DDR3 MCI BBLA96BC-A01_DIMS"
  round 0.4 smd mask+0.05: A1(3.2,-6) A2(2.4,-6) A3(1.6,-6) A7(-1.6,-6) A8(-2.4,-6) A9(-3.2,-6) B1(3.2,-5.2) B2(2.4,-5.2) B3(1.6,-5.2) B7(-1.6,-5.2) B8(-2.4,-5.2) B9(-3.2,-5.2) C1(3.2,-4.4) C2(2.4,-4.4) C3(1.6,-4.4) C7(-1.6,-4.4) C8(-2.4,-4.4) C9(-3.2,-4.4) D1(3.2,-3.6) D2(2.4,-3.6) D3(1.6,-3.6) D7(-1.6,-3.6) D8(-2.4,-3.6) D9(-3.2,-3.6) E1(3.2,-2.8) E2(2.4,-2.8) E3(1.6,-2.8) E7(-1.6,-2.8) E8(-2.4,-2.8) E9(-3.2,-2.8) F1(3.2,-2) F2(2.4,-2) F3(1.6,-2) F7(-1.6,-2) F8(-2.4,-2) F9(-3.2,-2) G1(3.2,-1.2) G2(2.4,-1.2) G3(1.6,-1.2) G7(-1.6,-1.2) G8(-2.4,-1.2) G9(-3.2,-1.2) H1(3.2,-0.4) H2(2.4,-0.4) H3(1.6,-0.4) H7(-1.6,-0.4) H8(-2.4,-0.4) H9(-3.2,-0.4) J1(3.2,0.4) J2(2.4,0.4) J3(1.6,0.4) J7(-1.6,0.4) J8(-2.4,0.4) J9(-3.2,0.4) K1(3.2,1.2) K2(2.4,1.2) K3(1.6,1.2) K7(-1.6,1.2) K8(-2.4,1.2) K9(-3.2,1.2) L1(3.2,2) L2(2.4,2) L3(1.6,2) L7(-1.6,2) L8(-2.4,2) L9(-3.2,2) M1(3.2,2.8) M2(2.4,2.8) M3(1.6,2.8) M7(-1.6,2.8) M8(-2.4,2.8) M9(-3.2,2.8) N1(3.2,3.6) N2(2.4,3.6) N3(1.6,3.6) N7(-1.6,3.6) N8(-2.4,3.6) N9(-3.2,3.6) P1(3.2,4.4) P2(2.4,4.4) P3(1.6,4.4) P7(-1.6,4.4) P8(-2.4,4.4) P9(-3.2,4.4) R1(3.2,5.2) R2(2.4,5.2) R3(1.6,5.2) R7(-1.6,5.2) R8(-2.4,5.2) R9(-3.2,5.2) T1(3.2,6) T2(2.4,6) T3(1.6,6) T7(-1.6,6) T8(-2.4,6) T9(-3.2,6)
  silkscreen extent -7.15,-12.5 7.15,12.5, body extent -35.45,-12.5 35.45,22, height 4.6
